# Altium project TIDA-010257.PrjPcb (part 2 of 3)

## Sheet EMCInputFilter.SchDoc: EMC Input Filter
size 431 x 279 mm; Date: Not shown in title block; ApprovedBy: Not shown in title block; CheckedBy: Not shown in title block; Author: Not shown in title block; CompanyName: Not shown in title block; Engineer: Not shown in title block; Organization: Not shown in title block; Address1: Not shown in title block; Address2: Not shown in title block; Address3: Not shown in title block; Address4: Not shown in title block; DocumentNumber: 1; Revision: Use project parameter SCH_Rev; SheetNumber: 3; SheetTotal: 11; PageSetup: Record=PageOptions¦CenterHorizontal=True¦CenterVertical=True¦PrintScale=1.00¦XCorrection=1.00¦YCorrection=1.00¦PrintKind=0¦BorderSize=5000000¦LeftOffset=0¦BottomOffset=0¦Orientation=2¦PaperLength=1000¦PaperWidth=1000¦Scale=100¦PaperSource=15¦PrintQuality=600¦MediaType=1¦DitherType=10¦PaperKind=Letter¦PrintScaleMode=1
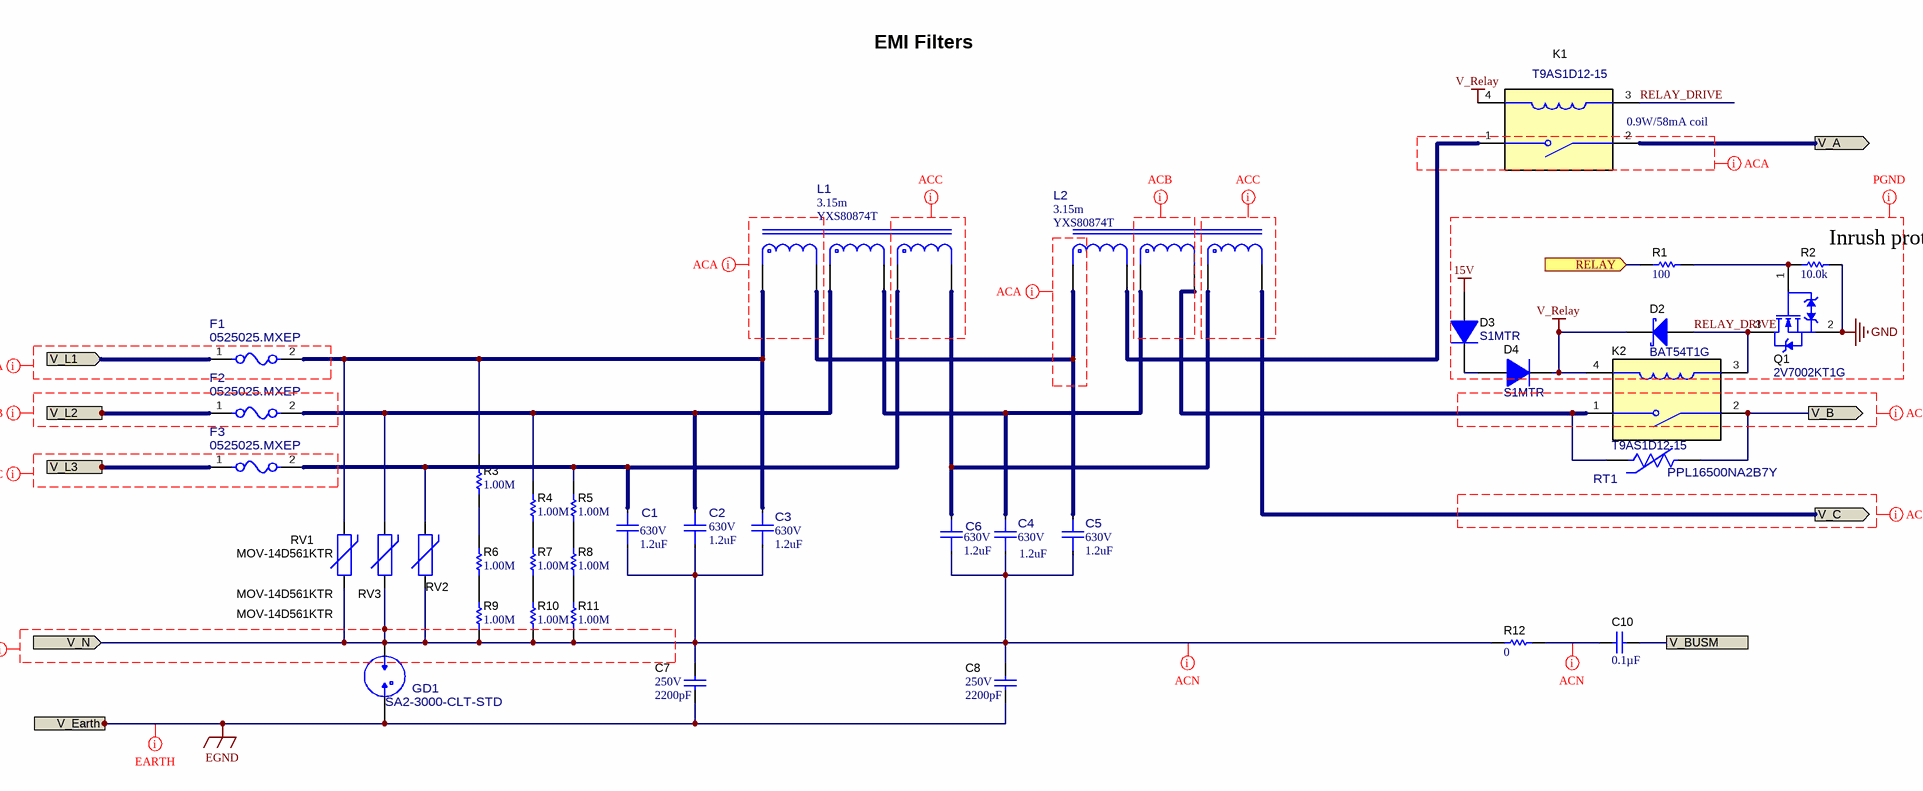
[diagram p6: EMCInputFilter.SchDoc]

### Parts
C1  VDC_V: 630V  ValueDisplayed: 1.2uF  [FP-890334027012CS_RADIAL-MFG]  (hidden comment: 890334027012CS)
C2  VDC_V: 630V  ValueDisplayed: 1.2uF  [FP-890334027012CS_RADIAL-MFG]  (hidden comment: 890334027012CS)
C3  VDC_V: 630V  ValueDisplayed: 1.2uF  [FP-890334027012CS_RADIAL-MFG]  (hidden comment: 890334027012CS)
C4  VDC_V: 630V  ValueDisplayed: 1.2uF  [FP-890334027012CS_RADIAL-MFG]  (hidden comment: 890334027012CS)
C5  VDC_V: 630V  ValueDisplayed: 1.2uF  [FP-890334027012CS_RADIAL-MFG]  (hidden comment: 890334027012CS)
C6  VDC_V: 630V  ValueDisplayed: 1.2uF  [FP-890334027012CS_RADIAL-MFG]  (hidden comment: 890334027012CS)
C7  VDC_V: 250V  ValueDisplayed: 2200pF  [CAPRD1000W60D900H1200]  (hidden comment: DE1E3KX222MA4BL01)
C8  VDC_V: 250V  ValueDisplayed: 2200pF  [CAPRD1000W60D900H1200]  (hidden comment: DE1E3KX222MA4BL01)
C10  ValueDisplayed: 0.1µF  [WCAP-FTXX_P15PL20_1800x600]  (hidden comment: 890334025017)
D2  BAT54T1G  [SOD-123]
D3  S1MTR  [SMA]
D4  S1MTR  [SMA]
F1  0525025.MXEP  [FP-0525025.MXEP_AXIAL-MFG]
F2  0525025.MXEP  [FP-0525025.MXEP_AXIAL-MFG]
F3  0525025.MXEP  [FP-0525025.MXEP_AXIAL-MFG]
GD1  SA2-3000-CLT-STD  [FP-SA2-3000-CLT-STD_AXIAL-MFG]
K1  T9AS1D12-15  [Relay_T9AS1D12]
K2  T9AS1D12-15  [Relay_T9AS1D12]
L1  DCR_ohm: 3.15m  [FP-YXS80874T_PTH_CMC_66MM0_56MM0-MFG]  (hidden comment: YXS80874T)
L2  DCR_ohm: 3.15m  [FP-YXS80874T_PTH_CMC_66MM0_56MM0-MFG]  (hidden comment: YXS80874T)
Q1  2V7002KT1G  [SOT-23]
R1  ValueDisplayed: 100  [0603]  (hidden comment: RC0603FR-07100RL)
R2  ValueDisplayed: 10.0k  [0603]  (hidden comment: RC0603FR-0710KL)
R3  ValueDisplayed: 1.00M  [0805_HV]  (hidden comment: ERJ-6ENF1004V)
R4  ValueDisplayed: 1.00M  [0805_HV]  (hidden comment: ERJ-6ENF1004V)
R5  ValueDisplayed: 1.00M  [0805_HV]  (hidden comment: ERJ-6ENF1004V)
R6  ValueDisplayed: 1.00M  [0805_HV]  (hidden comment: ERJ-6ENF1004V)
R7  ValueDisplayed: 1.00M  [0805_HV]  (hidden comment: ERJ-6ENF1004V)
R8  ValueDisplayed: 1.00M  [0805_HV]  (hidden comment: ERJ-6ENF1004V)
R9  ValueDisplayed: 1.00M  [0805_HV]  (hidden comment: ERJ-6ENF1004V)
R10  ValueDisplayed: 1.00M  [0805_HV]  (hidden comment: ERJ-6ENF1004V)
R11  ValueDisplayed: 1.00M  [0805_HV]  (hidden comment: ERJ-6ENF1004V)
R12  ValueDisplayed: 0  [0603]  (hidden comment: RC0603JR-070RL)
RT1  PPL16500NA2B7Y  [FP-PPL16500NA2B7Y_RADIAL-MFG]
RV1  MOV-14D561KTR  [Bourns_MOV-14D561K]
RV2  MOV-14D561KTR  [Bourns_MOV-14D561K]
RV3  MOV-14D561KTR  [Bourns_MOV-14D561K]

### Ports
RELAY (in), V_A (out), V_B (out), V_BUSM, V_C (out), V_Earth (in), V_L1 (in), V_L2 (in), V_L3 (in), V_N (in)

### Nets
15V: D3.2(A)
EGND: C7.2 C8.2 GD1.1 ; port V_Earth
GND: Q1.2(S) R2.2  [project net VBUSN]
V_Relay: D2.1(K) D4.1(K) K1.4 K2.4
VBUSM: C10.2 ; port V_BUSM
RELAY: R1.2 ; port RELAY
RELAY_DRIVE: D2.2(A) K1.3 K2.3 Q1.3(D)
V_A: K1.2 ; port V_A
V_B: K2.2 RT1.2 ; port V_B
V_C: L2.6 ; port V_C
V_L1: F1.1 ; port V_L1
V_L2: F2.1 ; port V_L2
V_L3: F3.1 ; port V_L3
VN: C1.1 C2.1 C3.1 C4.1 C5.1 C6.1 C7.1 C8.1 GD1.2 R9.1 R10.1 R11.1 R12.2 RV1.1 RV2.1 RV3.1 ; port V_N
NetC1_2: C1.2 F3.2 L1.5 R5.2 RV2.2
NetC2_2: C2.2 F2.2 L1.3 R4.2 RV3.2
NetC3_2: C3.2 F1.2 L1.1 R3.2 RV1.2
NetC4_2: C4.2 L1.4 L2.3
NetC5_2: C5.2 L1.2 L2.1
NetC6_2: C6.2 L1.6 L2.5
NetC10_1: C10.1 R12.1
NetD3_1: D3.1(K) D4.2(A)
NetK1_1: K1.1 L2.2
NetK2_1: K2.1 L2.4 RT1.1
NetQ1_1: Q1.1(G) R1.1 R2.1
NetR3_1: R3.1 R6.2
NetR4_1: R4.1 R7.2
NetR5_1: R5.1 R8.2
NetR6_1: R6.1 R9.2
NetR7_1: R7.1 R10.2
NetR8_1: R8.1 R11.2

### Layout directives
net class ACA: (no net found under the mark)
net class ACB: (no net found under the mark)
net class ACC: (no net found under the mark)
net class ACN: (no net found under the mark), NetC10_1, VN
net class EARTH: EGND
net class PGND: 15V, GND, RELAY_DRIVE, V_Relay

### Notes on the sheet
- EMI Filters
- (near K1) 0.9W/58mA coil
- Inrush protect

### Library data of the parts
C1-C6 = CMP-0090546-1: 1.2µF Film Capacitor 310V  Polypropylene (PP), Metallized Radial; Manufacturer: Wurth Electronics; AEC Qualified: No; Tolerance_%: 10%; SizeZ_mm: 22.5mm
C7 C8 = CMP-0009601-1: CAP, CERM, 2200 pF, 250 V, +/- 20%, E, Cap, 7x12x9 mm; Manufacturer: MuRata; TaMin_C: -25°C; Polarized: N; SizeAreaWB_mm2: 121.5; Value1: Unknown; U/M: EA; Value: 2200pF; TaMax_C: 85°C; SizeZ_mm: 12.5; SizeX_mm: 11.5; SizeY_mm: 7; SizeArea_mm2: 80.5; Cap_F: 2.2nF; AEC Category: Q200
C10 = CMP-0860742-1: CAP, Film, 0.1 µF, 310 VAC/ VDC,+/- 10%, TH; Manufacturer: Wurth Elektronik; VAC: 310; SizeZ_mm: 12.5; Cap_F: 100nF; Polarized: N; SizeArea_mm2: 108; SizeX_mm: 18; TaMax_C: 105°C; SizeAreaWB_mm2: 160; Value: 0.1uF; Cap_Case: 18x6x12mm; TaMin_C: -40°C; AEC Category: Q200; SizeY_mm: 6
D2 = CMP-0028457-2: Diode, Schottky, 30 V, 0.2 A, SOD-123; Manufacturer: ON Semiconductor; SizeArea_mm2: 6.545; Io_A: 200mA; SizeX_mm: 3.85; Value1: 0.2A; SizeY_mm: 1.7; AEC Category: Q101; Vf_V: 800mV; TJmax_C: 125°C; Green_Lifecycle: Not Set; RJC_CperW: 174; Value: 30V; Value2: 0.8V; SizeAreaWB_mm2: 13.095; Green_REACh: Incomplete; SizeZ_mm: 1.35
D3 D4 = CMP-0078438-2: Diode, Standard Recovery Rectifier, 1000 V, 1 A, SMA; Manufacturer: SMC Diode Solutions; Vf_V: 1.1V; TJmax_C: 175°C; SizeZ_mm: 2.87; SizeY_mm: 2.92; AEC Qualified: N; Vr_V: 1kV; Value1: 1A; SizeAreaWB_mm2: 37.3428; SizeArea_mm2: 16.3228; Value: 1000V; AEC Category: Q101; SizeX_mm: 5.59
F1-F3 = CMP-0090478-2: Manufacturer: Littelfuse; SizeZ_mm: 7.285mm; Fuse Interrupt Dc Current: 10000A; AEC Qualified: Yes; Res_ohm: 0.0038Ω; Fuse I2T: 320A2Sec; Fuse Current: 25A; AEC Grade: Grade 1; Interrupt_DC: 10kA; VDC_V: 450V
GD1 = CMP-0089811-1: Gas Discharge Tube 3000V 5000A (5kA) ±20% 2 Pole Through Hole; Manufacturer: Bourns; SizeZ_mm: 8.6mm; AEC Qualified: No
K1 K2 = CMP-0078608-2: Relay, SPST-NO (1 Form A), 30 A, 15 V, TH; Manufacturer: TE Connectivity; Contact Rating_A: 30A; Turn On Voltage (Max)_VDC: 11.25V; Coil Power_W: 1W; Coil Resistance_ohm: 225; SizeAreaWB_mm2: 1015.6293; Time Operate (s): 15ms; Coil Current_A: 66.7mA; SizeZ_mm: 20.4; SizeX_mm: 32.51; SizeY_mm: 27.43; SizeArea_mm2: 891.7493; Turn Off Voltage (Min)_VDC: 1.5V; Coil Type: Non Latching; Coil Voltage_VDC: 15V
L1 L2 = CMP-0122552-1: 3 PHASES COMMON MODE CHOKE; Manufacturer: YAXIN ELECTRONICS; SizeZ_mm: 66mm; AEC Qualified: No
Q1 = CMP-0000777-1: MOSFET, N-CH, 60 V, 0.32 A, AEC-Q101, SOT-23; Alternate Manufacturer: None; Manufacturer: ON Semiconductor; SizeZ_mm: 1.1; ChType: N; Value2: 0.7 nC; Value1: 2; VdsMax_V: 60V; SizeX_mm: 2.5; SizeY_mm: 3; Vgs_V: 20V; AEC Qualified: Y; Value: 60V; SizeArea_mm2: 7.5; AEC Category: Q101; IdsMax_A: 320mA; SizeAreaWB_mm2: 14; U/M: EA; QgTyp_nC: 0.7
R1 = CMP-0022736-4: RES, 100, 1%, 0.1 W, 0603; Manufacturer: Yageo; Power_W: 100mW; TempCo: 100 ppm/C; Value_Code: 100R; Value: 100; EIA_Code: E96; SizeX_mm: 1.6; SizeY_mm: 0.8; SizeZ_mm: 1; Value2: 0.1W; SizeArea_mm2: 1.28; AEC Qualified: N; VDC_V: 75V; AEC Category: Q200; SizeAreaWB_mm2: 4.68
R2 = CMP-0022746-5: RES, 10.0 k, 1%, 0.1 W, 0603; Manufacturer: Yageo; Power_W: 100mW; TempCo: 100 ppm/C; Value_Code: 10k0; Value: 10.0k; EIA_Code: E96; Res_ohm: 10k; SizeX_mm: 1.6; SizeY_mm: 0.8; SizeZ_mm: 1; Value2: 0.1W; SizeArea_mm2: 1.28; AEC Qualified: N; VDC_V: 75V; AEC Category: Q200; SizeAreaWB_mm2: 4.68
R3-R11 = CMP-0021522-3: RES, 1.00 M, 1%, 0.125 W, AEC-Q200 Grade 0, 0805; Manufacturer: Panasonic; Power_W: 125mW; TempCo: 100 ppm/C; Value_Code: 1M00; Value: 1.00Meg; EIA_Code: E96; Res_ohm: 1M; SizeX_mm: 2; SizeY_mm: 1.25; SizeZ_mm: 1.45; Value2: 0.125W; SizeArea_mm2: 2.5; AEC Qualified: Y; AEC Category: Q200; AEC Grade: 0; SizeAreaWB_mm2: 6.75
R12 = CMP-0025885-5: RES, 0, 5%, 0.1 W, 0603; Manufacturer: Yageo; Power_W: 100mW; TempCo: 200 ppm/C; Value_Code: 0000; Value: 0; EIA_Code: E24; SizeX_mm: 1.6; SizeZ_mm: 1; Value2: 0.1W; SizeArea_mm2: 1.28; AEC Qualified: N; VDC_V: 75V; AEC Category: Q200; SizeY_mm: 0.8; SizeAreaWB_mm2: 4.68
RT1 = CMP-0123150-1: Ceramic PTC Thermistor; Manufacturer: Thinking Electronic; SizeZ_mm: 21.5mm; Value: 50Ω; AEC Qualified: No; Tolerance_%: 30%; VDC_V: 270V
RV1-RV3 = CMP-0065393-2: VARISTOR 560V 4.5KA, TH; Manufacturer: Bourns; SizeAreaWB_mm2: 148.0; SizeZ_mm: 22.0; SizeX_mm: 16.5; SizeY_mm: 6.0; SizeArea_mm2: 99.0

## Sheet InputVoltageSensing.SchDoc: Input Voltage Sensing
size A4; Date: Not shown in title block; ApprovedBy: Not shown in title block; CheckedBy: Not shown in title block; Author: Not shown in title block; CompanyName: Not shown in title block; DrawnBy: Hely Zhang; Engineer: Not shown in title block; Organization: Not shown in title block; Address1: Not shown in title block; Address2: Not shown in title block; Address3: Not shown in title block; Address4: Not shown in title block; DocumentNumber: 1; Revision: Use project parameter SCH_Rev; SheetNumber: 7; SheetTotal: 11; PageSetup: Record=PageOptions¦CenterHorizontal=True¦CenterVertical=True¦PrintScale=1.00¦XCorrection=1.00¦YCorrection=1.00¦PrintKind=0¦BorderSize=5000000¦LeftOffset=0¦BottomOffset=0¦Orientation=2¦PaperLength=1000¦PaperWidth=1000¦Scale=100¦PaperSource=15¦PrintQuality=600¦MediaType=1¦DitherType=10¦PaperKind=Letter¦PrintScaleMode=1
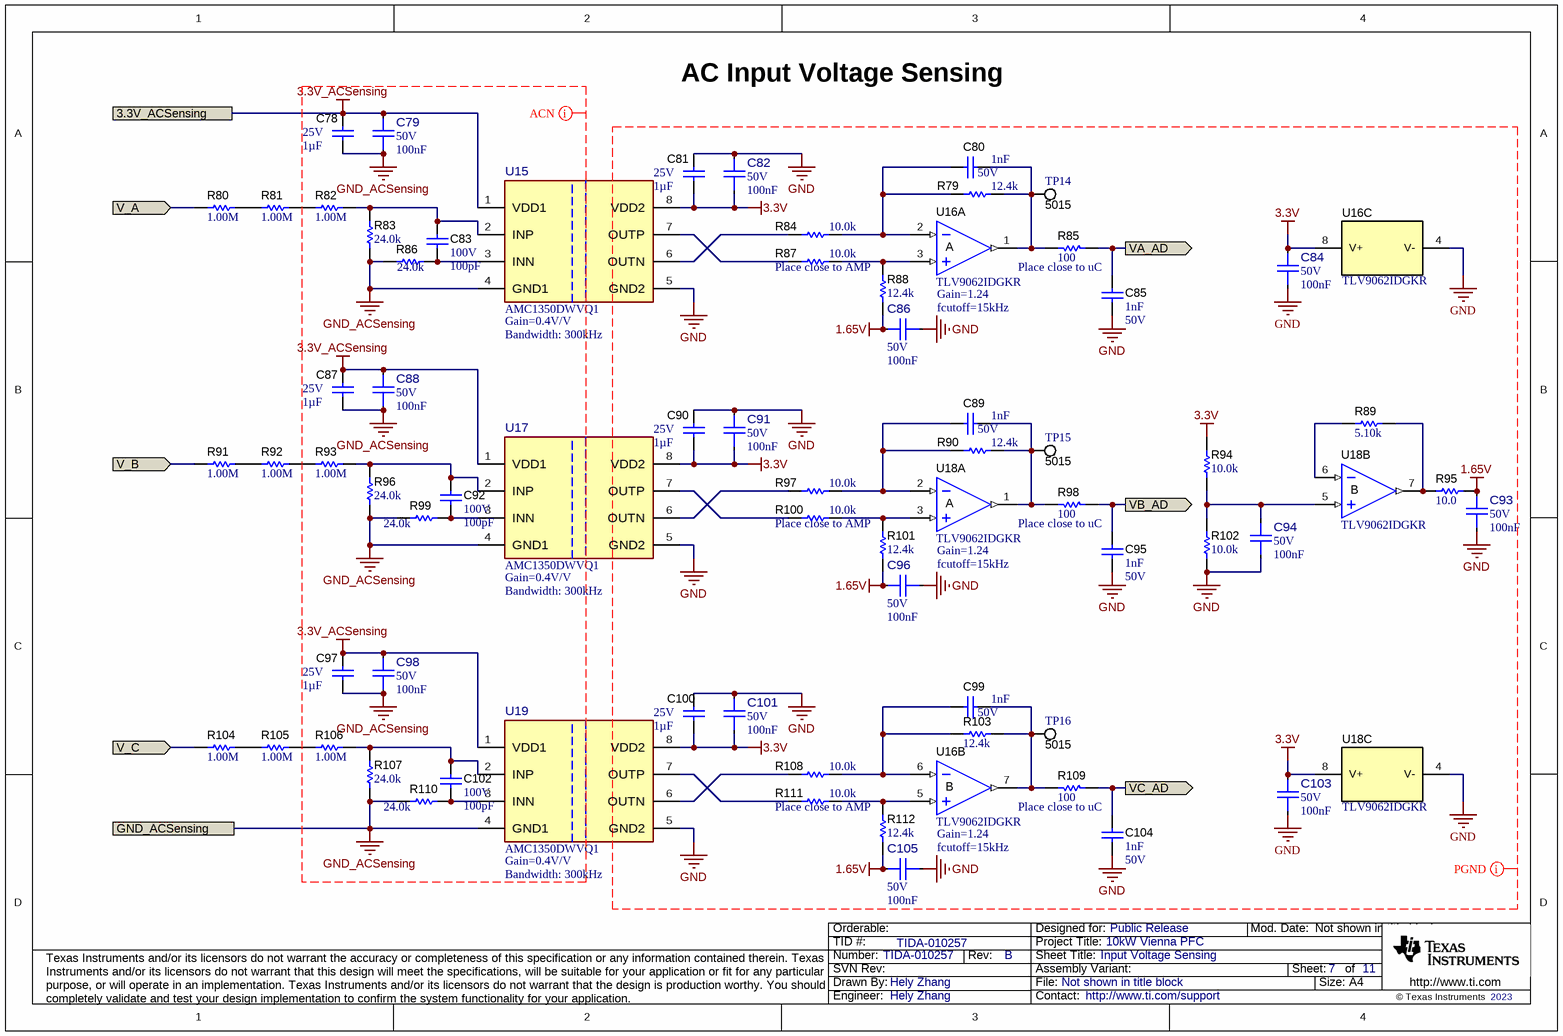
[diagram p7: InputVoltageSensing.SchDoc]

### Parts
C78  VDC_V: 25V  Cap_F: 1µF  [0603]  (hidden comment: GRJ188R71E105KE11D)
C79  VDC_V: 50V  Cap_F: 100nF  [FP-GCM188R71H104KA57J_0603-MFG]  (hidden comment: GCM188R71H104KA57J)
C80  Cap_F: 1nF  VDC_V: 50V  [0603]  (hidden comment: GRM188R71H102KA01D)
C81  VDC_V: 25V  Cap_F: 1µF  [0603]  (hidden comment: GRJ188R71E105KE11D)
C82  VDC_V: 50V  Cap_F: 100nF  [FP-GCM188R71H104KA57J_0603-MFG]  (hidden comment: GCM188R71H104KA57J)
C83  VDC_V: 100V  ValueDisplayed: 100pF  [0603]  (hidden comment: GRM1885C2A101JA01D)
C84  VDC_V: 50V  Cap_F: 100nF  [FP-GCM188R71H104KA57J_0603-MFG]  (hidden comment: GCM188R71H104KA57J)
C85  Cap_F: 1nF  VDC_V: 50V  [0603]  (hidden comment: GRM188R71H102KA01D)
C86  VDC_V: 50V  Cap_F: 100nF  [FP-GCM188R71H104KA57J_0603-MFG]  (hidden comment: GCM188R71H104KA57J)
C87  VDC_V: 25V  Cap_F: 1µF  [0603]  (hidden comment: GRJ188R71E105KE11D)
C88  VDC_V: 50V  Cap_F: 100nF  [FP-GCM188R71H104KA57J_0603-MFG]  (hidden comment: GCM188R71H104KA57J)
C89  Cap_F: 1nF  VDC_V: 50V  [0603]  (hidden comment: GRM188R71H102KA01D)
C90  VDC_V: 25V  Cap_F: 1µF  [0603]  (hidden comment: GRJ188R71E105KE11D)
C91  VDC_V: 50V  Cap_F: 100nF  [FP-GCM188R71H104KA57J_0603-MFG]  (hidden comment: GCM188R71H104KA57J)
C92  VDC_V: 100V  ValueDisplayed: 100pF  [0603]  (hidden comment: GRM1885C2A101JA01D)
C93  VDC_V: 50V  Cap_F: 100nF  [FP-GCM188R71H104KA57J_0603-MFG]  (hidden comment: GCM188R71H104KA57J)
C94  VDC_V: 50V  Cap_F: 100nF  [FP-GCM188R71H104KA57J_0603-MFG]  (hidden comment: GCM188R71H104KA57J)
C95  Cap_F: 1nF  VDC_V: 50V  [0603]  (hidden comment: GRM188R71H102KA01D)
C96  VDC_V: 50V  Cap_F: 100nF  [FP-GCM188R71H104KA57J_0603-MFG]  (hidden comment: GCM188R71H104KA57J)
C97  VDC_V: 25V  Cap_F: 1µF  [0603]  (hidden comment: GRJ188R71E105KE11D)
C98  VDC_V: 50V  Cap_F: 100nF  [FP-GCM188R71H104KA57J_0603-MFG]  (hidden comment: GCM188R71H104KA57J)
C99  Cap_F: 1nF  VDC_V: 50V  [0603]  (hidden comment: GRM188R71H102KA01D)
C100  VDC_V: 25V  Cap_F: 1µF  [0603]  (hidden comment: GRJ188R71E105KE11D)
C101  VDC_V: 50V  Cap_F: 100nF  [FP-GCM188R71H104KA57J_0603-MFG]  (hidden comment: GCM188R71H104KA57J)
C102  VDC_V: 100V  ValueDisplayed: 100pF  [0603]  (hidden comment: GRM1885C2A101JA01D)
C103  VDC_V: 50V  Cap_F: 100nF  [FP-GCM188R71H104KA57J_0603-MFG]  (hidden comment: GCM188R71H104KA57J)
C104  Cap_F: 1nF  VDC_V: 50V  [0603]  (hidden comment: GRM188R71H102KA01D)
C105  VDC_V: 50V  Cap_F: 100nF  [FP-GCM188R71H104KA57J_0603-MFG]  (hidden comment: GCM188R71H104KA57J)
R79  ValueDisplayed: 12.4k  [0603]  (hidden comment: RC0603FR-0712K4L)
R80  ValueDisplayed: 1.00M  [0805_HV]  (hidden comment: ERJ-6ENF1004V)
R81  ValueDisplayed: 1.00M  [0805_HV]  (hidden comment: ERJ-6ENF1004V)
R82  ValueDisplayed: 1.00M  [0805_HV]  (hidden comment: ERJ-6ENF1004V)
R83  ValueDisplayed: 24.0k  [0603]  (hidden comment: RC0603FR-0724KL)
R84  ValueDisplayed: 10.0k  [0603]  (hidden comment: RC0603FR-0710KL)
R85  ValueDisplayed: 100  [0603]  (hidden comment: RC0603FR-07100RL)
R86  ValueDisplayed: 24.0k  [0603]  (hidden comment: RC0603FR-0724KL)
R87  ValueDisplayed: 10.0k  [0603]  (hidden comment: RC0603FR-0710KL)
R88  ValueDisplayed: 12.4k  [0603]  (hidden comment: RC0603FR-0712K4L)
R89  ValueDisplayed: 5.10k  [0603]  (hidden comment: RC0603FR-075K1L)
R90  ValueDisplayed: 12.4k  [0603]  (hidden comment: RC0603FR-0712K4L)
R91  ValueDisplayed: 1.00M  [0805_HV]  (hidden comment: ERJ-6ENF1004V)
R92  ValueDisplayed: 1.00M  [0805_HV]  (hidden comment: ERJ-6ENF1004V)
R93  ValueDisplayed: 1.00M  [0805_HV]  (hidden comment: ERJ-6ENF1004V)
R94  ValueDisplayed: 10.0k  [0603]  (hidden comment: RC0603FR-0710KL)
R95  ValueDisplayed: 10.0  [0603]  (hidden comment: RC0603FR-0710RL)
R96  ValueDisplayed: 24.0k  [0603]  (hidden comment: RC0603FR-0724KL)
R97  ValueDisplayed: 10.0k  [0603]  (hidden comment: RC0603FR-0710KL)
R98  ValueDisplayed: 100  [0603]  (hidden comment: RC0603FR-07100RL)
R99  ValueDisplayed: 24.0k  [0603]  (hidden comment: RC0603FR-0724KL)
R100  ValueDisplayed: 10.0k  [0603]  (hidden comment: RC0603FR-0710KL)
R101  ValueDisplayed: 12.4k  [0603]  (hidden comment: RC0603FR-0712K4L)
R102  ValueDisplayed: 10.0k  [0603]  (hidden comment: RC0603FR-0710KL)
R103  ValueDisplayed: 12.4k  [0603]  (hidden comment: RC0603FR-0712K4L)
R104  ValueDisplayed: 1.00M  [0805_HV]  (hidden comment: ERJ-6ENF1004V)
R105  ValueDisplayed: 1.00M  [0805_HV]  (hidden comment: ERJ-6ENF1004V)
R106  ValueDisplayed: 1.00M  [0805_HV]  (hidden comment: ERJ-6ENF1004V)
R107  ValueDisplayed: 24.0k  [0603]  (hidden comment: RC0603FR-0724KL)
R108  ValueDisplayed: 10.0k  [0603]  (hidden comment: RC0603FR-0710KL)
R109  ValueDisplayed: 100  [0603]  (hidden comment: RC0603FR-07100RL)
R110  ValueDisplayed: 24.0k  [0603]  (hidden comment: RC0603FR-0724KL)
R111  ValueDisplayed: 10.0k  [0603]  (hidden comment: RC0603FR-0710KL)
R112  ValueDisplayed: 12.4k  [0603]  (hidden comment: RC0603FR-0712K4L)
TP14  5015  [Testpoint_Keystone_Miniature]
TP15  5015  [Testpoint_Keystone_Miniature]
TP16  5015  [Testpoint_Keystone_Miniature]
U15  AMC1350DWVQ1  [DWV0008A-MFG]
U16  TLV9062IDGKR  [DGK0008A_N]  (parts A,B,C of 3)
U17  AMC1350DWVQ1  [DWV0008A-MFG]
U18  TLV9062IDGKR  [DGK0008A_N]  (parts A,B,C of 3)
U19  AMC1350DWVQ1  [DWV0008A-MFG]

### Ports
3.3V_ACSensing, GND_ACSensing, V_A (in), V_B (in), V_C (in), VA_AD (out), VB_AD (out), VC_AD (out)

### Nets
1.65V: C86.2 C93.2 C96.2 C105.2 R88.1 R95.2 R101.1 R112.1
3.3V: C81.2 C82.1 C84.2 C90.2 C91.1 C100.2 C101.1 C103.2 R94.2 U15.8(VDD2) U16.8(V+) U17.8(VDD2) U18.8(V+) U19.8(VDD2)
3.3V_ACSensing: C78.1 C79.2 C87.1 C88.2 C97.1 C98.2 U15.1(VDD1) U17.1(VDD1) U19.1(VDD1) ; port 3.3V_ACSensing
GND: C81.1 C82.2 C84.1 C85.1 C86.1 C90.1 C91.2 C93.1 C94.1 C95.1 C96.1 C100.1 C101.2 C103.1 C104.1 C105.1 R102.1 U15.5(GND2) U16.4(V-) U17.5(GND2) U18.4(V-) U19.5(GND2)  [project net VBUSN]
GND_ACSensing: C78.2 C79.1 C87.2 C88.1 C97.2 C98.1 R83.1 R86.2 R96.2 R99.2 R107.2 R110.2 U15.4(GND1) U17.4(GND1) U19.4(GND1) ; port GND_ACSensing
V_A: R80.1 ; port V_A
V_B: R91.1 ; port V_B
V_C: R104.1 ; port V_C
VA_AD: C85.2 R85.1 ; port VA_AD
VB_AD: C95.2 R98.1 ; port VB_AD
VC_AD: C104.2 R109.1 ; port VC_AD
NetC80_1: C80.1 R79.2 R85.2 TP14.1 U16.1(OUT)
NetC80_2: C80.2 R79.1 R84.2 U16.2(IN-)
NetC83_1: C83.1 R82.2 R83.2 U15.2(INP)
NetC83_2: C83.2 R86.1 U15.3(INN)
NetC89_1: C89.1 R90.2 R98.2 TP15.1 U18.1(OUT)
NetC89_2: C89.2 R90.1 R97.2 U18.2(IN-)
NetC92_1: C92.1 R93.2 R96.1 U17.2(INP)
NetC92_2: C92.2 R99.1 U17.3(INN)
NetC94_2: C94.2 R94.1 R102.2 U18.5(IN+)
NetC99_1: C99.1 R103.2 R109.2 TP16.1 U16.7(OUT)
NetC99_2: C99.2 R103.1 R108.2 U16.6(IN-)
NetC102_1: C102.1 R106.2 R107.1 U19.2(INP)
NetC102_2: C102.2 R110.1 U19.3(INN)
NetR80_2: R80.2 R81.1
NetR81_2: R81.2 R82.1
NetR84_1: R84.1 U15.6(OUTN)
NetR87_1: R87.1 U15.7(OUTP)
NetR87_2: R87.2 R88.2 U16.3(IN+)
NetR89_1: R89.1 R95.1 U18.7(OUT)
NetR89_2: R89.2 U18.6(IN-)
NetR91_2: R91.2 R92.1
NetR92_2: R92.2 R93.1
NetR97_1: R97.1 U17.6(OUTN)
NetR100_1: R100.1 U17.7(OUTP)
NetR100_2: R100.2 R101.2 U18.3(IN+)
NetR104_2: R104.2 R105.1
NetR105_2: R105.2 R106.1
NetR108_1: R108.1 U19.6(OUTN)
NetR111_1: R111.1 U19.7(OUTP)
NetR111_2: R111.2 R112.2 U16.5(IN+)

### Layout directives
net class ACN: 3.3V_ACSensing, GND_ACSensing
net class PGND: 1.65V, 3.3V, GND

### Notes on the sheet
- AC Input Voltage Sensing
- Place close to AMP
- Gain=1.24
- fcutoff=15kHz
- Place close to uC
- (near U15) Gain=0.4V/V
- (near U15) Bandwidth: 300kHz
- (near U17) Gain=0.4V/V
- (near U17) Bandwidth: 300kHz
- (near U19) Gain=0.4V/V
- (near U19) Bandwidth: 300kHz

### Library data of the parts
C78 C81 C87 C90 C97 C100 = CMP-0079720-2: CAP, CERM, 1 µF, 25 V,+/- 10%, X7R, 0603; Manufacturer: MuRata; AEC Category: Q200; TaMin_C: -55°C; AEC Qualified: N; SizeAreaWB_mm2: 4.68; SizeArea_mm2: 1.28; Value: 1uF; SizeZ_mm: 1; SizeX_mm: 1.6; U/M: EA; MFG_Status: TI_Obsolete; SizeY_mm: 0.8; TaMax_C: 125°C
C79 C82 C84 C86 C88 C91 C93 C94 C96 C98 C101 C103 C105 = CMP-0095617-1: 0603 50 V 0.1 uF X7R ±10% Tolerance SMT Multilayer Ceramic Capacitor; Manufacturer: Murata; TempCo: 15%; SizeZ_mm: 0.9mm; AEC Qualified: No; ValueDisplayed: 0.1uF; Value: 100nF
C80 C85 C89 C95 C99 C104 = CMP-0007432-5: CAP, CERM, 1000 pF, 50 V, +/- 10%, X7R, 0603; Manufacturer: MuRata; TaMin_C: -55°C; Polarized: N; SizeAreaWB_mm2: 4.68; Value1: Unknown; U/M: EA; Value: 1000pF; TaMax_C: 125°C; SizeZ_mm: 1; SizeX_mm: 1.6; SizeY_mm: 0.8; SizeArea_mm2: 1.28; AEC Category: Q200
C83 C92 C102 = CMP-0007237-4: CAP, CERM, 100 pF, 100 V, +/- 5%, C0G/NP0, 0603; Manufacturer: MuRata; TaMin_C: -55°C; Polarized: N; SizeAreaWB_mm2: 4.68; Value1: Unknown; U/M: EA; Value: 100pF; TaMax_C: 125°C; SizeZ_mm: 1; SizeX_mm: 1.6; SizeY_mm: 0.8; SizeArea_mm2: 1.28; AEC Category: Q200
R79 R88 R90 R101 R103 R112 = CMP-0022777-5: RES, 12.4 k, 1%, 0.1 W, 0603; Manufacturer: Yageo; Power_W: 100mW; TempCo: 100 ppm/C; Value_Code: 12k4; Value: 12.4k; EIA_Code: E96; SizeX_mm: 1.6; SizeY_mm: 0.8; SizeZ_mm: 1; Value2: 0.1W; SizeArea_mm2: 1.28; AEC Qualified: N; VDC_V: 75V; AEC Category: Q200; SizeAreaWB_mm2: 4.68
R80-R82 R91-R93 R104-R106 = CMP-0021522-3: as R3-R11 on sheet EMCInputFilter
R83 R86 R96 R99 R107 R110 = CMP-0022945-5: RES, 24.0 k, 1%, 0.1 W, 0603; Manufacturer: Yageo; Power_W: 100mW; TempCo: 100 ppm/C; Value_Code: 24k0; Value: 24.0k; Res_ohm: 24k; SizeX_mm: 1.6; SizeY_mm: 0.8; SizeZ_mm: 1; Value2: 0.1W; SizeArea_mm2: 1.28; AEC Qualified: N; VDC_V: 75V; AEC Category: Q200; SizeAreaWB_mm2: 4.68
R84 R87 R94 R97 R100 R102 R108 R111 = CMP-0022746-5: as R2 on sheet EMCInputFilter
R85 R98 R109 = CMP-0022736-4: as R1 on sheet EMCInputFilter
R89 = CMP-0023198-5: RES, 5.10 k, 1%, 0.1 W, 0603; Manufacturer: Yageo; Power_W: 100mW; TempCo: 100 ppm/C; Value_Code: 5k10; Value: 5.10k; Res_ohm: 5.1k; SizeX_mm: 1.6; SizeY_mm: 0.8; SizeZ_mm: 1; Value2: 0.1W; SizeArea_mm2: 1.28; AEC Qualified: N; VDC_V: 75V; AEC Category: Q200; SizeAreaWB_mm2: 4.68
R95 = CMP-0022751-4: RES, 10.0, 1%, 0.1 W, 0603; Manufacturer: Yageo; Power_W: 100mW; TempCo: 100 ppm/C; Value_Code: 10R0; Value: 10.0; EIA_Code: E96; Res_ohm: 10; SizeX_mm: 1.6; SizeY_mm: 0.8; SizeZ_mm: 1; Value2: 0.1W; SizeArea_mm2: 1.28; AEC Qualified: N; VDC_V: 75V; AEC Category: Q200; SizeAreaWB_mm2: 4.68
TP14-TP16 = CMP-0055152-2: Test Point, Miniature, SMT; Manufacturer: Keystone Electronics; CT: TRUE; Green_Lifecycle: Active; Green_REACh: Passed; CNHeader: FALSE
U15 U17 U19 = CMP-0092814-1: Precision, ±5-V Input, Reinforced Isolated Amplifier; Manufacturer: Texas Instruments; Bandwidth: 275kHz; Input Bias Current: 0.0035uA; SizeZ_mm: 2.8mm; Output Current Per Channel: 14mA; TaMax_C: +125°C; Input Offset Voltage: 0.4mV; TaMin_C: -55°C; Standoff Height: 0.36mm; Min Supply Voltage: 3V; TJmax_C: +150°C; AEC Qualified: No; Max Supply Voltage: 5.5V; Number Of Channels: 1
U16 U18 = CMP-0084063-1: 10-MHz, Low-Noise, RRIO, CMOS Operational Amplifier for Cost-Sensitive Systems, DGK0008A (VSSOP-8); Manufacturer: Texas Instruments; Alternate PartNumber: TLV9062IDGKT; Rating: Catalog; SizeAreaWB_mm2: 23.6; SizeArea_mm2: 14.7; AEC Qualified: N; AEC Category: Q200; SizeZ_mm: 1.1; SizeY_mm: 3; CompType: IC; SizeX_mm: 4.9

## Sheet OutputVoltageSensing.SchDoc: OutputVoltageSensing
size A4; Date: Not shown in title block; ApprovedBy: Not shown in title block; CheckedBy: Not shown in title block; Author: Not shown in title block; CompanyName: Not shown in title block; DrawnBy: Hely Zhang; Engineer: Not shown in title block; Organization: Not shown in title block; Address1: Not shown in title block; Address2: Not shown in title block; Address3: Not shown in title block; Address4: Not shown in title block; DocumentNumber: 1; Revision: Use project parameter SCH_Rev; SheetNumber: 8; SheetTotal: 11; PageSetup: Record=PageOptions¦CenterHorizontal=True¦CenterVertical=True¦PrintScale=1.00¦XCorrection=1.00¦YCorrection=1.00¦PrintKind=0¦BorderSize=5000000¦LeftOffset=0¦BottomOffset=0¦Orientation=2¦PaperLength=1000¦PaperWidth=1000¦Scale=100¦PaperSource=15¦PrintQuality=600¦MediaType=1¦DitherType=10¦PaperKind=Letter¦PrintScaleMode=1
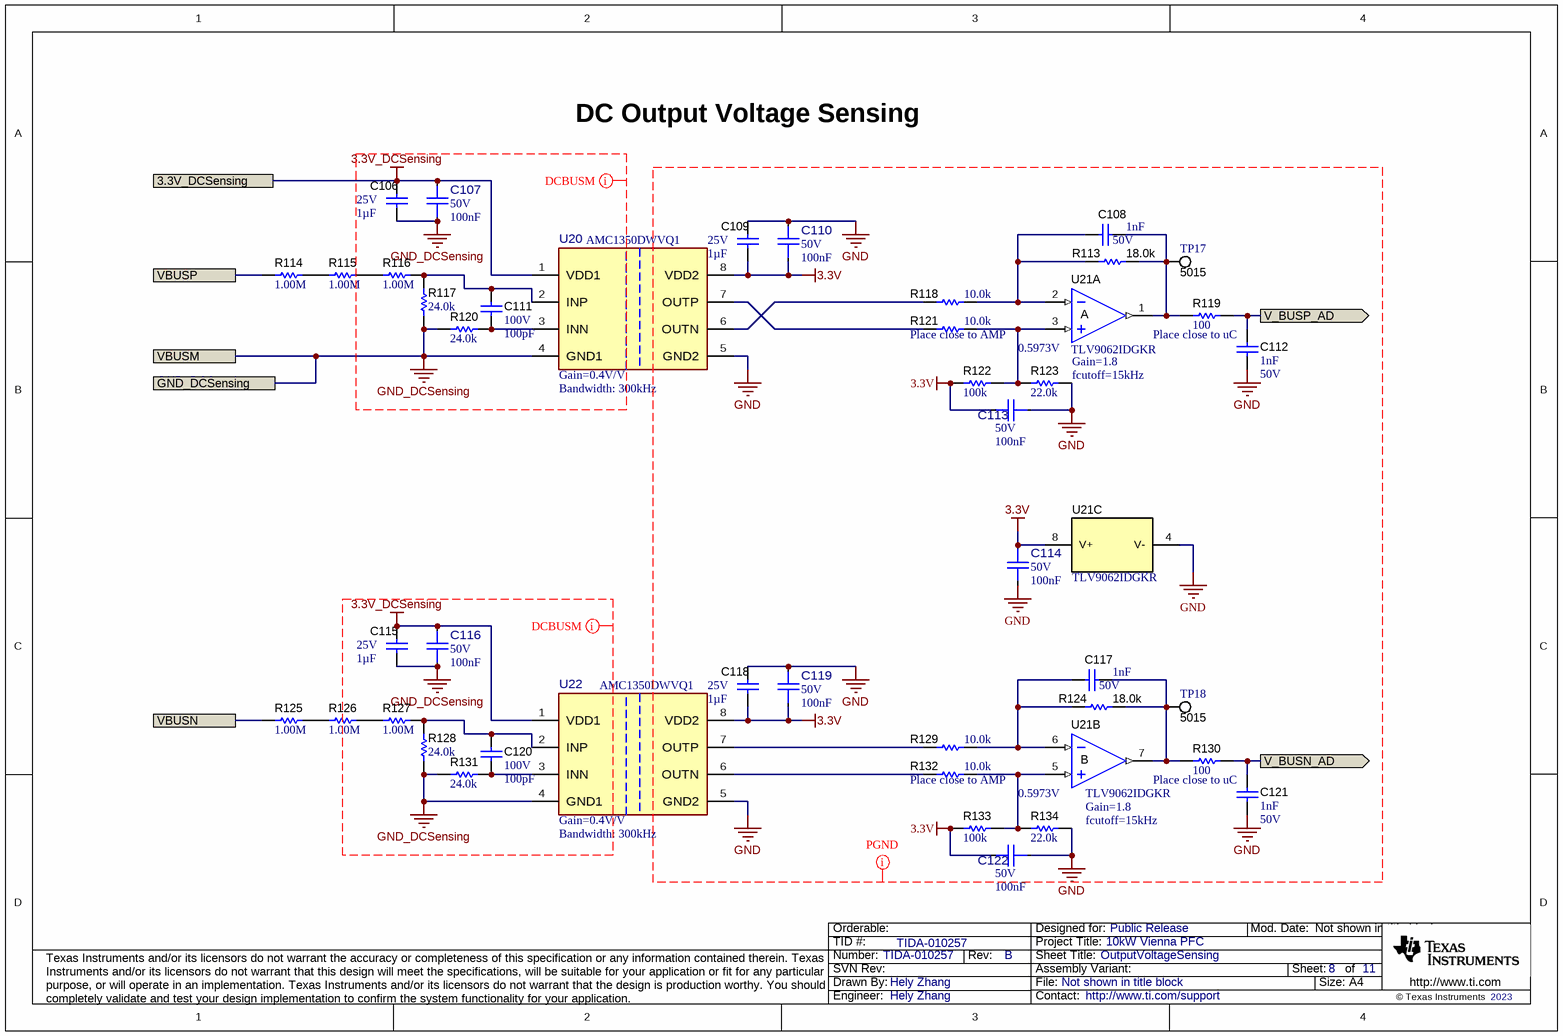
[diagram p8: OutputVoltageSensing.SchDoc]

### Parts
C106  VDC_V: 25V  Cap_F: 1µF  [0603]  (hidden comment: GRJ188R71E105KE11D)
C107  VDC_V: 50V  Cap_F: 100nF  [FP-GCM188R71H104KA57J_0603-MFG]  (hidden comment: GCM188R71H104KA57J)
C108  Cap_F: 1nF  VDC_V: 50V  [0603]  (hidden comment: GRM188R71H102KA01D)
C109  VDC_V: 25V  Cap_F: 1µF  [0603]  (hidden comment: GRJ188R71E105KE11D)
C110  VDC_V: 50V  Cap_F: 100nF  [FP-GCM188R71H104KA57J_0603-MFG]  (hidden comment: GCM188R71H104KA57J)
C111  VDC_V: 100V  ValueDisplayed: 100pF  [0603]  (hidden comment: GRM1885C2A101JA01D)
C112  Cap_F: 1nF  VDC_V: 50V  [0603]  (hidden comment: GRM188R71H102KA01D)
C113  VDC_V: 50V  Cap_F: 100nF  [FP-GCM188R71H104KA57J_0603-MFG]  (hidden comment: GCM188R71H104KA57J)
C114  VDC_V: 50V  Cap_F: 100nF  [FP-GCM188R71H104KA57J_0603-MFG]  (hidden comment: GCM188R71H104KA57J)
C115  VDC_V: 25V  Cap_F: 1µF  [0603]  (hidden comment: GRJ188R71E105KE11D)
C116  VDC_V: 50V  Cap_F: 100nF  [FP-GCM188R71H104KA57J_0603-MFG]  (hidden comment: GCM188R71H104KA57J)
C117  Cap_F: 1nF  VDC_V: 50V  [0603]  (hidden comment: GRM188R71H102KA01D)
C118  VDC_V: 25V  Cap_F: 1µF  [0603]  (hidden comment: GRJ188R71E105KE11D)
C119  VDC_V: 50V  Cap_F: 100nF  [FP-GCM188R71H104KA57J_0603-MFG]  (hidden comment: GCM188R71H104KA57J)
C120  VDC_V: 100V  ValueDisplayed: 100pF  [0603]  (hidden comment: GRM1885C2A101JA01D)
C121  Cap_F: 1nF  VDC_V: 50V  [0603]  (hidden comment: GRM188R71H102KA01D)
C122  VDC_V: 50V  Cap_F: 100nF  [FP-GCM188R71H104KA57J_0603-MFG]  (hidden comment: GCM188R71H104KA57J)
R113  ValueDisplayed: 18.0k  [0603]  (hidden comment: RC0603FR-0718KL)
R114  ValueDisplayed: 1.00M  [0805_HV]  (hidden comment: ERJ-6ENF1004V)
R115  ValueDisplayed: 1.00M  [0805_HV]  (hidden comment: ERJ-6ENF1004V)
R116  ValueDisplayed: 1.00M  [0805_HV]  (hidden comment: ERJ-6ENF1004V)
R117  ValueDisplayed: 24.0k  [0603]  (hidden comment: RC0603FR-0724KL)
R118  ValueDisplayed: 10.0k  [0603]  (hidden comment: RC0603FR-0710KL)
R119  ValueDisplayed: 100  [0603]  (hidden comment: RC0603FR-07100RL)
R120  ValueDisplayed: 24.0k  [0603]  (hidden comment: RC0603FR-0724KL)
R121  ValueDisplayed: 10.0k  [0603]  (hidden comment: RC0603FR-0710KL)
R122  ValueDisplayed: 100k  [0603]  (hidden comment: RC0603FR-07100KL)
R123  ValueDisplayed: 22.0k  [0603]  (hidden comment: RC0603FR-0722KL)
R124  ValueDisplayed: 18.0k  [0603]  (hidden comment: RC0603FR-0718KL)
R125  ValueDisplayed: 1.00M  [0805_HV]  (hidden comment: ERJ-6ENF1004V)
R126  ValueDisplayed: 1.00M  [0805_HV]  (hidden comment: ERJ-6ENF1004V)
R127  ValueDisplayed: 1.00M  [0805_HV]  (hidden comment: ERJ-6ENF1004V)
R128  ValueDisplayed: 24.0k  [0603]  (hidden comment: RC0603FR-0724KL)
R129  ValueDisplayed: 10.0k  [0603]  (hidden comment: RC0603FR-0710KL)
R130  ValueDisplayed: 100  [0603]  (hidden comment: RC0603FR-07100RL)
R131  ValueDisplayed: 24.0k  [0603]  (hidden comment: RC0603FR-0724KL)
R132  ValueDisplayed: 10.0k  [0603]  (hidden comment: RC0603FR-0710KL)
R133  ValueDisplayed: 100k  [0603]  (hidden comment: RC0603FR-07100KL)
R134  ValueDisplayed: 22.0k  [0603]  (hidden comment: RC0603FR-0722KL)
TP17  5015  [Testpoint_Keystone_Miniature]
TP18  5015  [Testpoint_Keystone_Miniature]
U20  AMC1350DWVQ1  [DWV0008A-MFG]
U21  TLV9062IDGKR  [DGK0008A_N]  (parts A,B,C of 3)
U22  AMC1350DWVQ1  [DWV0008A-MFG]

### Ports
3.3V_DCSensing, GND_DCSensing, V_BUSN_AD (out), V_BUSP_AD (out), VBUSM, VBUSN, VBUSP

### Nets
3.3V: C109.2 C110.1 C113.2 C114.1 C118.2 C119.1 C122.2 R122.2 R133.2 U20.8(VDD2) U21.8(V+) U22.8(VDD2)
3.3V_DCSensing: C106.1 C107.2 C115.1 C116.2 U20.1(VDD1) U22.1(VDD1) ; port 3.3V_DCSensing
GND: C109.1 C110.2 C112.1 C113.1 C114.2 C118.1 C119.2 C121.1 C122.1 R123.2 R125.1 R134.2 U20.5(GND2) U21.4(V-) U22.5(GND2) ; port VBUSN  [project net VBUSN]
GND_DCSensing: C106.2 C107.1 C115.2 C116.1 R117.2 R120.2 R128.1 R131.1 U20.4(GND1) U22.4(GND1) ; port VBUSM, port GND_DCSensing  [project net VBUSM]
V_BUSN_AD: C121.2 R130.2 ; port V_BUSN_AD
V_BUSP_AD: C112.2 R119.2 ; port V_BUSP_AD
VBUSP: R114.1 ; port VBUSP
NetC108_1: C108.1 R113.1 R119.1 TP17.1 U21.1(OUT)
NetC108_2: C108.2 R113.2 R118.2 U21.2(IN-)
NetC111_1: C111.1 R116.2 R117.1 U20.2(INP)
NetC111_2: C111.2 R120.1 U20.3(INN)
NetC117_1: C117.1 R124.1 R130.1 TP18.1 U21.7(OUT)
NetC117_2: C117.2 R124.2 R129.2 U21.6(IN-)
NetC120_1: C120.1 R127.2 R128.2 U22.2(INP)
NetC120_2: C120.2 R131.2 U22.3(INN)
NetR114_2: R114.2 R115.1
NetR115_2: R115.2 R116.1
NetR118_1: R118.1 U20.6(OUTN)
NetR121_1: R121.1 U20.7(OUTP)
NetR121_2: R121.2 R122.1 R123.1 U21.3(IN+)
NetR125_2: R125.2 R126.1
NetR126_2: R126.2 R127.1
NetR129_1: R129.1 U22.7(OUTP)
NetR132_1: R132.1 U22.6(OUTN)
NetR132_2: R132.2 R133.1 R134.1 U21.5(IN+)

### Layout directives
net class DCBUSM: 3.3V_DCSensing, GND_DCSensing
net class PGND: 3.3V, GND

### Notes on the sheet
- DC Output Voltage Sensing
- (near U20) Gain=0.4V/V
- (near R121) Place close to AMP
- 0.5973V
- Gain=1.8
- (near R123) fcutoff=15kHz
- (near C112) Place close to uC
- (near U20) Bandwidth: 300kHz
- (near R132) Place close to AMP
- (near C121) Place close to uC
- (near U22) Gain=0.4V/V
- (near U22) Bandwidth: 300kHz
- fcutoff=15kHz

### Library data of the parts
C106 C109 C115 C118 = CMP-0079720-2: as C78 on sheet InputVoltageSensing
C107 C110 C113 C114 C116 C119 C122 = CMP-0095617-1: as C79 on sheet InputVoltageSensing
C108 C112 C117 C121 = CMP-0007432-5: as C80 on sheet InputVoltageSensing
C111 C120 = CMP-0007237-4: as C83 on sheet InputVoltageSensing
R113 R124 = CMP-0022852-5: RES, 18.0 k, 1%, 0.1 W, 0603; Manufacturer: Yageo; Power_W: 100mW; TempCo: 100 ppm/C; Value_Code: 18k0; Value: 18.0k; Res_ohm: 18k; SizeX_mm: 1.6; SizeY_mm: 0.8; SizeZ_mm: 1; Value2: 0.1W; SizeArea_mm2: 1.28; AEC Qualified: N; VDC_V: 75V; AEC Category: Q200; SizeAreaWB_mm2: 4.68
R114-R116 R125-R127 = CMP-0021522-3: as R3-R11 on sheet EMCInputFilter
R117 R120 R128 R131 = CMP-0022945-5: as R83 on sheet InputVoltageSensing
R118 R121 R129 R132 = CMP-0022746-5: as R2 on sheet EMCInputFilter
R119 R130 = CMP-0022736-4: as R1 on sheet EMCInputFilter
R122 R133 = CMP-0022735-5: RES, 100 k, 1%, 0.1 W, 0603; Manufacturer: Yageo; Power_W: 100mW; TempCo: 100 ppm/C; Value: 100k; EIA_Code: E96; SizeX_mm: 1.6; SizeY_mm: 0.8; SizeZ_mm: 1; Value2: 0.1W; SizeArea_mm2: 1.28; AEC Qualified: N; VDC_V: 75V; AEC Category: Q200; SizeAreaWB_mm2: 4.68
R123 R134 = CMP-0022925-5: RES, 22.0 k, 1%, 0.1 W, 0603; Manufacturer: Yageo; Power_W: 100mW; TempCo: 100 ppm/C; Value_Code: 22k0; Value: 22.0k; Res_ohm: 22k; SizeX_mm: 1.6; SizeY_mm: 0.8; SizeZ_mm: 1; Value2: 0.1W; SizeArea_mm2: 1.28; AEC Qualified: N; VDC_V: 75V; AEC Category: Q200; SizeAreaWB_mm2: 4.68
TP17 TP18 = CMP-0055152-2: as TP14-TP16 on sheet InputVoltageSensing
U20 U22 = CMP-0092814-1: as U15 on sheet InputVoltageSensing
U21 = CMP-0084063-1: as U16 on sheet InputVoltageSensing

## Sheet Controller.SchDoc: Controller
size A4; Date: Not shown in title block; ApprovedBy: Not shown in title block; CheckedBy: Not shown in title block; Author: Not shown in title block; CompanyName: Not shown in title block; DrawnBy: Hely Zhang; Engineer: Not shown in title block; Organization: Not shown in title block; Address1: Not shown in title block; Address2: Not shown in title block; Address3: Not shown in title block; Address4: Not shown in title block; DocumentNumber: 1; Revision: Use project parameter SCH_Rev; SheetNumber: 9; SheetTotal: 11; PageSetup: Record=PageOptions¦CenterHorizontal=True¦CenterVertical=True¦PrintScale=1.00¦XCorrection=1.00¦YCorrection=1.00¦PrintKind=0¦BorderSize=5000000¦LeftOffset=0¦BottomOffset=0¦Orientation=2¦PaperLength=1000¦PaperWidth=1000¦Scale=100¦PaperSource=15¦PrintQuality=600¦MediaType=1¦DitherType=10¦PaperKind=Letter¦PrintScaleMode=1
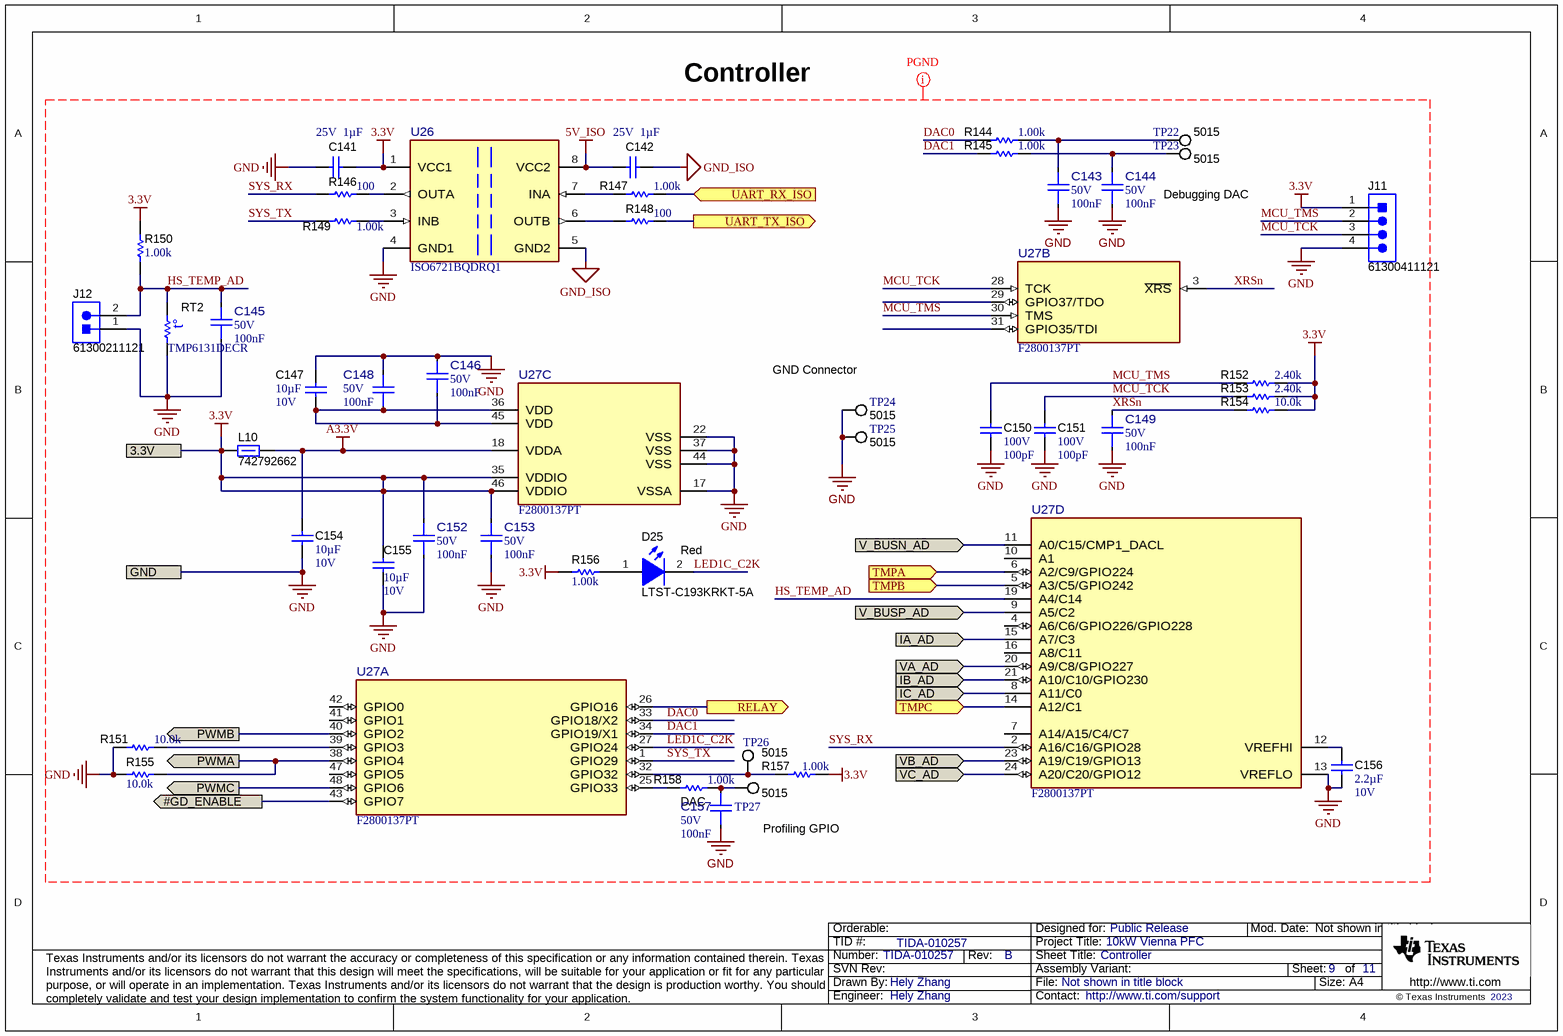
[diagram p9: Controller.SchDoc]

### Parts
C141  VDC_V: 25V  Cap_F: 1µF  [0603]  (hidden comment: GRJ188R71E105KE11D)
C142  VDC_V: 25V  Cap_F: 1µF  [0603]  (hidden comment: GRJ188R71E105KE11D)
C143  VDC_V: 50V  Cap_F: 100nF  [FP-GCM188R71H104KA57J_0603-MFG]  (hidden comment: GCM188R71H104KA57J)
C144  VDC_V: 50V  Cap_F: 100nF  [FP-GCM188R71H104KA57J_0603-MFG]  (hidden comment: GCM188R71H104KA57J)
C145  VDC_V: 50V  Cap_F: 100nF  [FP-GCM188R71H104KA57J_0603-MFG]  (hidden comment: GCM188R71H104KA57J)
C146  VDC_V: 50V  Cap_F: 100nF  [FP-GCM188R71H104KA57J_0603-MFG]  (hidden comment: GCM188R71H104KA57J)
C147  Cap_F: 10µF  VDC_V: 10V  [0603]  (hidden comment: GRM188Z71A106MA73D)
C148  VDC_V: 50V  Cap_F: 100nF  [FP-GCM188R71H104KA57J_0603-MFG]  (hidden comment: GCM188R71H104KA57J)
C149  VDC_V: 50V  Cap_F: 100nF  [FP-GCM188R71H104KA57J_0603-MFG]  (hidden comment: GCM188R71H104KA57J)
C150  VDC_V: 100V  ValueDisplayed: 100pF  [0603]  (hidden comment: GRM1885C2A101JA01D)
C151  VDC_V: 100V  ValueDisplayed: 100pF  [0603]  (hidden comment: GRM1885C2A101JA01D)
C152  VDC_V: 50V  Cap_F: 100nF  [FP-GCM188R71H104KA57J_0603-MFG]  (hidden comment: GCM188R71H104KA57J)
C153  VDC_V: 50V  Cap_F: 100nF  [FP-GCM188R71H104KA57J_0603-MFG]  (hidden comment: GCM188R71H104KA57J)
C154  Cap_F: 10µF  VDC_V: 10V  [0603]  (hidden comment: GRM188Z71A106MA73D)
C155  Cap_F: 10µF  VDC_V: 10V  [0603]  (hidden comment: GRM188Z71A106MA73D)
C156  Cap_F: 2.2µF  VDC_V: 10V  [0603]  (hidden comment: GRM188R71A225KE15J)
C157  VDC_V: 50V  Cap_F: 100nF  [FP-GCM188R71H104KA57J_0603-MFG]  (hidden comment: GCM188R71H104KA57J)
D25  LTST-C193KRKT-5A  value Red  [LTST-C193_Red]
J11  61300411121  [WURTH_61300411121]
J12  61300211121  [WURTH_61300211121]
L10  742792662  [0603]
R144  ValueDisplayed: 1.00k  [0603]  (hidden comment: RC0603FR-071KL)
R145  ValueDisplayed: 1.00k  [0603]  (hidden comment: RC0603FR-071KL)
R146  ValueDisplayed: 100  [0603]  (hidden comment: RC0603FR-07100RL)
R147  ValueDisplayed: 1.00k  [0603]  (hidden comment: RC0603FR-071KL)
R148  ValueDisplayed: 100  [0603]  (hidden comment: RC0603FR-07100RL)
R149  ValueDisplayed: 1.00k  [0603]  (hidden comment: RC0603FR-071KL)
R150  ValueDisplayed: 1.00k  [0603]  (hidden comment: RC0603FR-071KL)
R151  ValueDisplayed: 10.0k  [0603]  (hidden comment: RC0603FR-0710KL)
R152  ValueDisplayed: 2.40k  [0603]  (hidden comment: RC0603FR-072K4L)
R153  ValueDisplayed: 2.40k  [0603]  (hidden comment: RC0603FR-072K4L)
R154  ValueDisplayed: 10.0k  [0603]  (hidden comment: RC0603FR-0710KL)
R155  ValueDisplayed: 10.0k  [0603]  (hidden comment: RC0603FR-0710KL)
R156  ValueDisplayed: 1.00k  [0603]  (hidden comment: RC0603FR-071KL)
R157  ValueDisplayed: 1.00k  [0603]  (hidden comment: RC0603FR-071KL)
R158  ValueDisplayed: 1.00k  [0603]  (hidden comment: RC0603FR-071KL)
RT2  TMP6131DECR  [DEC0002A]
TP22  5015  [Testpoint_Keystone_Miniature]
TP23  5015  [Testpoint_Keystone_Miniature]
TP24  5015  [Testpoint_Keystone_Miniature]
TP25  5015  [Testpoint_Keystone_Miniature]
TP26  5015  [Testpoint_Keystone_Miniature]
TP27  5015  [Testpoint_Keystone_Miniature]
U26  ISO6721BQDRQ1  [D0008A-MFG]
U27  F2800137PT  [PT0048A-MFG]  (parts A,B,C,D of 4)

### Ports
3.3V, #GD_ENABLE (out), GND, IA_AD (in), IB_AD (in), IC_AD (in), PWMA (out), PWMB (out), PWMC (out), RELAY (out), TMPA (in), TMPB (in), TMPC (in), UART_RX_ISO (in), UART_TX_ISO (out), V_BUSN_AD (in), V_BUSP_AD (in), VA_AD (in), VB_AD (in), VC_AD (in)

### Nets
3.3V: C141.2 C152.2 C153.2 C155.2 J11.1 L10.1 R150.2 R152.2 R153.2 R154.1 R156.1 R157.2 U26.1(VCC1) U27.35(VDDIO) U27.46(VDDIO) ; port 3.3V
5V_ISO: C142.1 U26.8(VCC2)
A3.3V: C154.1 L10.2 U27.18(VDDA)
GND: C141.1 C143.1 C144.1 C145.1 C146.2 C147.1 C148.2 C149.1 C150.2 C151.2 C152.1 C153.1 C154.2 C155.1 C156.2 C157.1 J11.4 J12.1 R151.2 R155.1 RT2.1 TP24.1 TP25.1 U26.4(GND1) U27.13(VREFLO) U27.17(VSSA) U27.22(VSS) U27.37(VSS) U27.44(VSS) ; port GND  [project net VBUSN]
GND_ISO: C142.2 U26.5(GND2)
#GD_ENABLE: U27.43(GPIO7) ; port #GD_ENABLE
DAC0: R144.1 U27.33(GPIO18/X2)
DAC1: R145.1 U27.34(GPIO19/X1)
HS_TEMP_AD: C145.2 J12.2 R150.1 RT2.2 U27.19(A4/C14)
IA_AD: U27.15(A7/C3) ; port IA_AD
IB_AD: U27.21(A10/C10/GPIO230) ; port IB_AD
IC_AD: U27.8(A11/C0) ; port IC_AD
LED1C_C2K: D25.2(K) U27.27(GPIO24)
MCU_TCK: C151.1 J11.3 R153.1 U27.28(TCK)
MCU_TMS: C150.1 J11.2 R152.1 U27.30(TMS)
PWMA: R155.2 U27.38(GPIO4) ; port PWMA
PWMB: U27.40(GPIO2) ; port PWMB
PWMC: U27.48(GPIO6) ; port PWMC
RELAY: U27.26(GPIO16) ; port RELAY
RX: R147.2 ; port UART_RX_ISO
SYS_RX: R146.1 U27.2(A16/C16/GPIO28)
SYS_TX: R149.1 U27.1(GPIO29)
TMPA: U27.6(A2/C9/GPIO224) ; port TMPA
TMPB: U27.5(A3/C5/GPIO242) ; port TMPB
TMPC: U27.14(A12/C1) ; port TMPC
TX: R148.2 ; port UART_TX_ISO
V_BUSN_AD: U27.11(A0/C15/CMP1_DACL) ; port V_BUSN_AD
V_BUSP_AD: U27.9(A5/C2) ; port V_BUSP_AD
VA_AD: U27.20(A9/C8/GPIO227) ; port VA_AD
VB_AD: U27.23(A19/C19/GPIO13) ; port VB_AD
VC_AD: U27.24(A20/C20/GPIO12) ; port VC_AD
XRSn: C149.2 R154.2 U27.3(~{XRS})
NetC143_2: C143.2 R144.2 TP22.1
NetC144_2: C144.2 R145.2 TP23.1
NetC146_1: C146.1 C147.2 C148.1 U27.36(VDD) U27.45(VDD)
NetC156_1: C156.1 U27.12(VREFHI)
NetC157_2: C157.2 R158.2 TP27.1
NetD25_1: D25.1(A) R156.2
NetR146_2: R146.2 U26.2(OUTA)
NetR147_1: R147.1 U26.7(INA)
NetR148_1: R148.1 U26.6(OUTB)
NetR149_2: R149.2 U26.3(INB)
NetR151_1: R151.1 U27.39(GPIO3)
NetR157_1: R157.1 TP26.1 U27.32(GPIO32)
NetR158_1: R158.1 U27.25(GPIO33)

Not connected (* = marked no-connect by the designer): U27 4(A6/C6/GPIO226/GPIO228) 7(A14/A15/C4/C7) 10(A1) 16(A8/C11) 29(GPIO37/TDO) 31(GPIO35/TDI) 41(GPIO1) 42(GPIO0) 47(GPIO5)

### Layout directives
net class PGND: 3.3V, 5V_ISO, A3.3V, DAC0, DAC1, GND, GND_ISO, HS_TEMP_AD, LED1C_C2K, MCU_TCK, MCU_TMS, SYS_RX, SYS_TX, XRSn

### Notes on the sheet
- Controller
- Debugging DAC
- (near TP24) GND Connector
- (near R158) DAC
- Profiling GPIO

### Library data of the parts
C141 C142 = CMP-0079720-2: as C78 on sheet InputVoltageSensing
C143-C146 C148 C149 C152 C153 C157 = CMP-0095617-1: as C79 on sheet InputVoltageSensing
C147 C154 C155 = CMP-0007497-5: CAP, CERM, 10 uF, 10 V, +/- 20%, X7R, 0603; Manufacturer: MuRata; TaMin_C: -55°C; Polarized: N; SizeAreaWB_mm2: 4.68; Value1: Unknown; U/M: EA; Value: 10uF; TaMax_C: 125°C; SizeZ_mm: 1; SizeX_mm: 1.6; SizeY_mm: 0.8; SizeArea_mm2: 1.28; AEC Category: Q200
C150 C151 = CMP-0007237-4: as C83 on sheet InputVoltageSensing
C156 = CMP-0084284-1: CAP, CERM, 2.2 µF, 10 V,+/- 10%, X7R, AEC-Q200 Grade 1, 0603; Manufacturer: MuRata; SizeAreaWB_mm2: 4.68; Polarized: N; AEC Qualified: Y; SizeX_mm: 1.6; SizeZ_mm: 1; SizeY_mm: 0.8; U/M: EA; TaMin_C: -55°C; Value: 2.2uF; AEC Category: Q200; TaMax_C: 125°C; SizeArea_mm2: 1.28
D25 = CMP-0079922-3: LED, Red, SMD; Manufacturer: Lite-On; SizeX_mm: 1.6; Value2: 2V; SizeY_mm: 0.8; Green_REACh: Incomplete; SizeAreaWB_mm2: 4.68; Green_Lifecycle: Not Set; Value1: W; Io_A: 5mA; Type: AlInGaP; SizeZ_mm: 0.45; Tjmax_C: 85°C; SizeArea_mm2: 1.28
J11 = CMP-0054798-2: Header, 2.54 mm, 4x1, Gold, TH; Manufacturer: Wurth Elektronik; Pitch_mm: 2.54; Gender: Male; Row_Count: 1; Cert_UL: Y; Shrouded: N
J12 = CMP-0054794-2: Header, 2.54 mm, 2x1, Gold, TH; Manufacturer: Wurth Elektronik; Shrouded: N; Gender: Male; Green_REACh: Passed; Pitch_mm: 2.54; Green_Lifecycle: Active; Row_Count: 1; Cert_UL: Y
L10 = CMP-0003201-2: Ferrite Bead, 1000 ohm @ 100 MHz, 0.6 A, 0603; Manufacturer: Wurth Elektronik; Ztyp@1GHz_Ohm: 185.971; ZTyp@100MHz_Ohm: 1k; SizeAreaWB_mm2: 4.68; DCR_ohm: 0.3; Value1: 0.3 ohm; Imax_A: 600mA; SizeZ_mm: 1; SizeX_mm: 1.6; SizeY_mm: 0.8; Value2: 0.6A; SizeArea_mm2: 1.28
R144 R145 R147 R149 R150 R156-R158 = CMP-0022895-5: RES, 1.00 k, 1%, 0.1 W, 0603; Manufacturer: Yageo; Power_W: 100mW; TempCo: 100 ppm/C; Value_Code: 1k00; Value: 1.00k; EIA_Code: E96; Res_ohm: 1k; SizeX_mm: 1.6; SizeY_mm: 0.8; SizeZ_mm: 1; Value2: 0.1W; SizeArea_mm2: 1.28; AEC Qualified: N; VDC_V: 75V; AEC Category: Q200; SizeAreaWB_mm2: 4.68
R146 R148 = CMP-0022736-4: as R1 on sheet EMCInputFilter
R151 R154 R155 = CMP-0022746-5: as R2 on sheet EMCInputFilter
R152 R153 = CMP-0022991-5: RES, 2.40 k, 1%, 0.1 W, 0603; Manufacturer: Yageo; Power_W: 100mW; TempCo: 100 ppm/C; Value_Code: 2k40; Value: 2.40k; Res_ohm: 2.4k; SizeX_mm: 1.6; SizeY_mm: 0.8; SizeZ_mm: 1; Value2: 0.1W; SizeArea_mm2: 1.28; AEC Qualified: N; VDC_V: 75V; AEC Category: Q200; SizeAreaWB_mm2: 4.68
RT2 = CMP-0084566-1: Thermistor, DEC0002A (X1SON-2); Alternate Manufacturer: Texas Instruments; Alternate PartNumber: TMP6131DECT; CompType: IC; AEC Category: Q200; SizeX_mm: 1; AEC Qualified: N; SizeZ_mm: 0.5; SizeArea_mm2: 0.6; SizeAreaWB_mm2: 3.2
TP22-TP27 = CMP-0055152-2: as TP14-TP16 on sheet InputVoltageSensing
U26 = CMP-0089949-1: Low Speed, General Purpose, Robust EMC, Dual-Channel Digital Isolators; Manufacturer: Texas Instruments; TJmax_C: +150°C; TaMin_C: -40°C; SizeZ_mm: 1.75mm; Min Supply Voltage: 1.71V; Standoff Height: 0.11mm; AEC Qualified: Yes; TaMax_C: +125°C; AEC Grade: Grade 1; Max Supply Voltage: 5.5V; Interface: LVCMOS
U27 = CMP-0096487-1: Real-Time Microcontrollers; Manufacturer: Texas Instruments; Number Of Pwm Channels: 14; Number Of Spi Channels: 1; Memory Type: FLASH; Frequency_Fixed: 120MHz; TaMin_C: -40°C; Number Of I2C Channels: 2; AEC Qualified: No; TaMax_C: +125°C; Number Of Adc Channels: 17; Ram Size: 36KBytes; Min Supply Voltage: 2.8V; Number Of Timers/Counters: 4; Core Architecture: TMS320C28x; Data Bus Width: 32bits; Number Of Uart Channels: 3; SizeZ_mm: 1.6mm; Memory Size: 256KBytes; Standoff Height: 0.5mm; Max Supply Voltage: 3.63V; Number Of I/Os: 25; Interface: I2C,SPI,UART,CAN,SCI,SMBus

## Sheet AuxPower.SchDoc: Auxillary Power Supply
size A4; Date: Not shown in title block; ApprovedBy: Not shown in title block; CheckedBy: Not shown in title block; Author: Not shown in title block; CompanyName: Not shown in title block; DrawnBy: Hely Zhang; Engineer: Not shown in title block; Organization: Not shown in title block; Address1: Not shown in title block; Address2: Not shown in title block; Address3: Not shown in title block; Address4: Not shown in title block; DocumentNumber: 1; Revision: Use project parameter SCH_Rev; SheetNumber: 5; SheetTotal: 11; PageSetup: Record=PageOptions¦CenterHorizontal=True¦CenterVertical=True¦PrintScale=1.00¦XCorrection=1.00¦YCorrection=1.00¦PrintKind=0¦BorderSize=5000000¦LeftOffset=0¦BottomOffset=0¦Orientation=2¦PaperLength=1000¦PaperWidth=1000¦Scale=100¦PaperSource=15¦PrintQuality=600¦MediaType=1¦DitherType=10¦PaperKind=Letter¦PrintScaleMode=1
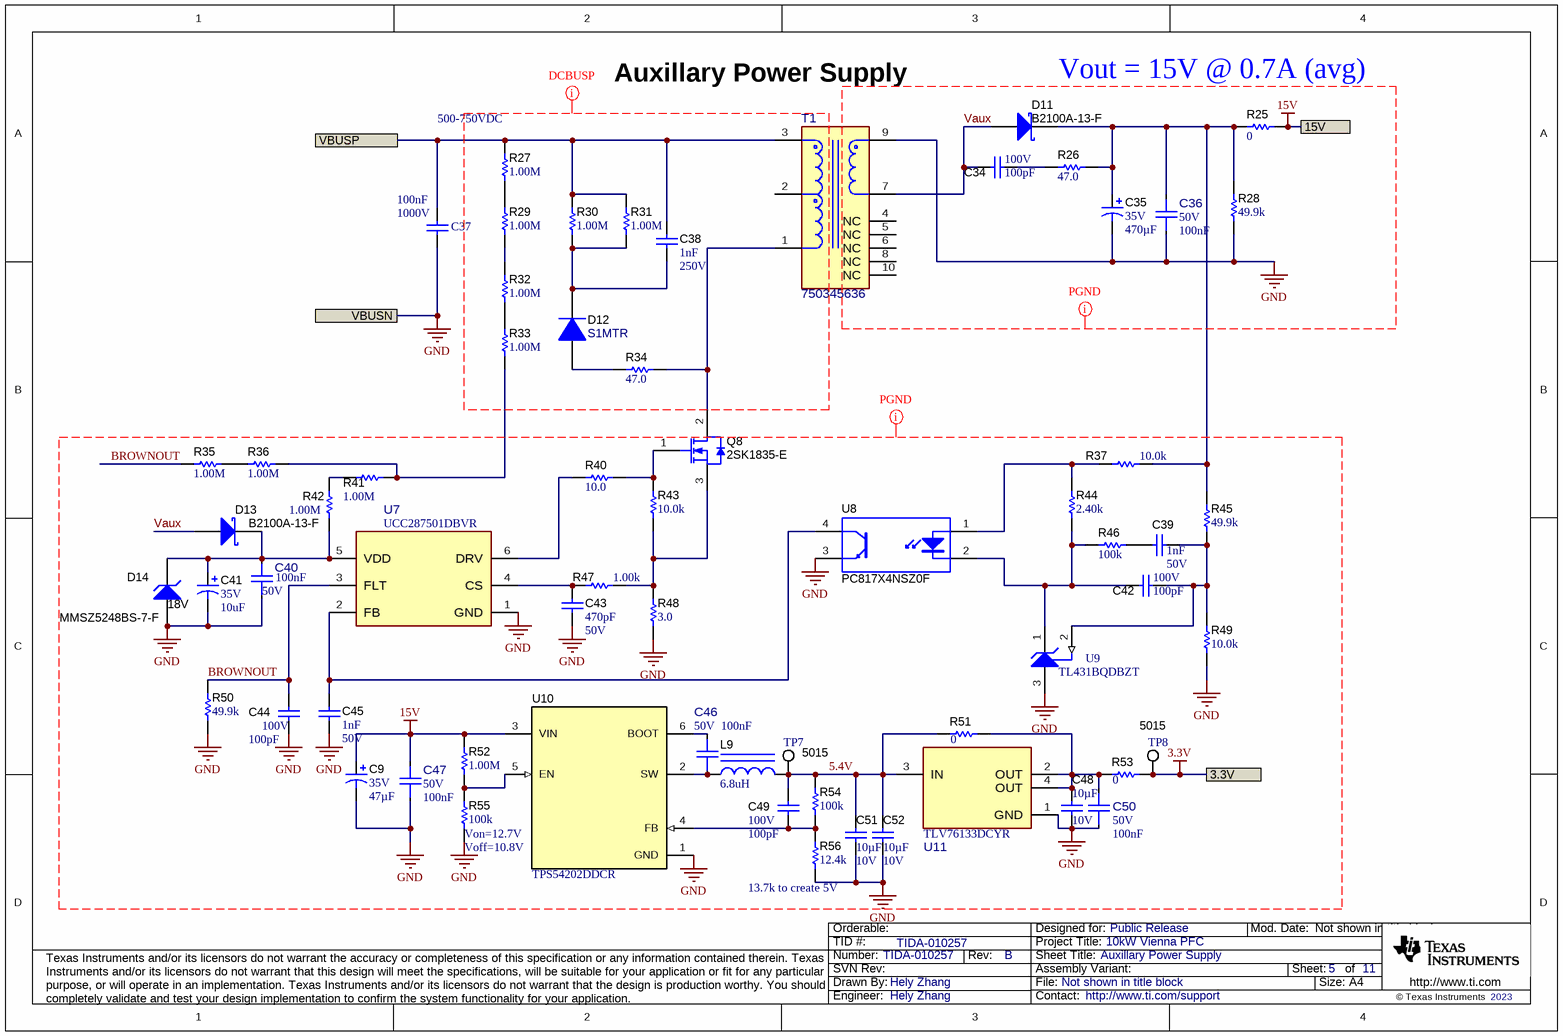
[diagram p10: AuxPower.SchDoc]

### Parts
C9  VDC_V: 35V  ValueDisplayed: 47µF  [Chemi-Con_500x1100]  (hidden comment: EKZN350ELL470ME11D)
C34  VDC_V: 100V  ValueDisplayed: 100pF  [0603]  (hidden comment: GRM1885C2A101JA01D)
C35  VDC_V: 35V  ValueDisplayed: 470µF  [ZLG_1000x2000]  (hidden comment: 35ZLG470MEFC10X20)
C36  VDC_V: 50V  Cap_F: 100nF  [FP-GCM188R71H104KA57J_0603-MFG]  (hidden comment: GCM188R71H104KA57J)
C37  Cap_F: 100nF  Rated Voltage (DC): 1000V  [WCAP-FTBE_L18W8.5H15]  (hidden comment: 890493425009CS)
C38  Cap_F: 1nF  VDC_V: 250V  [0805_HV]  (hidden comment: GRM21AR72E102KW01D)
C39  Cap_F: 1nF  VDC_V: 50V  [0603]  (hidden comment: GRM188R71H102KA01D)
C40  VDC_V: 50V  Cap_F: 100nF  [FP-GCM188R71H104KA57J_0603-MFG]  (hidden comment: GCM188R71H104KA57J)
C41  VDC_V: 35V  ValueDisplayed: 10uF  [PW_500x700]  (hidden comment: UPW1V100MDD6)
C42  VDC_V: 100V  ValueDisplayed: 100pF  [0603]  (hidden comment: GRM1885C2A101JA01D)
C43  Cap_F: 470pF  VDC_V: 50V  [0603]  (hidden comment: 885012206081)
C44  VDC_V: 100V  ValueDisplayed: 100pF  [0603]  (hidden comment: GRM1885C2A101JA01D)
C45  Cap_F: 1nF  VDC_V: 50V  [0603]  (hidden comment: GRM188R71H102KA01D)
C46  VDC_V: 50V  Cap_F: 100nF  [FP-GCM188R71H104KA57J_0603-MFG]  (hidden comment: GCM188R71H104KA57J)
C47  VDC_V: 50V  Cap_F: 100nF  [FP-GCM188R71H104KA57J_0603-MFG]  (hidden comment: GCM188R71H104KA57J)
C48  Cap_F: 10µF  VDC_V: 10V  [0603]  (hidden comment: GRM188Z71A106MA73D)
C49  VDC_V: 100V  ValueDisplayed: 100pF  [0603]  (hidden comment: GRM1885C2A101JA01D)
C50  VDC_V: 50V  Cap_F: 100nF  [FP-GCM188R71H104KA57J_0603-MFG]  (hidden comment: GCM188R71H104KA57J)
C51  Cap_F: 10µF  VDC_V: 10V  [0603]  (hidden comment: GRM188Z71A106MA73D)
C52  Cap_F: 10µF  VDC_V: 10V  [0603]  (hidden comment: GRM188Z71A106MA73D)
D11  B2100A-13-F  [SMA]
D12  S1MTR  [SMA]
D13  B2100A-13-F  [SMA]
D14  MMSZ5248BS-7-F  value 18V  [SOD-323]
L9  ValueDisplayed: 6.8uH  [WE-MAIA_3015]  (hidden comment: 78438335068)
Q8  2SK1835-E  [TO-3P]
R25  ValueDisplayed: 0  [0603]  (hidden comment: RC0603JR-070RL)
R26  ValueDisplayed: 47.0  [1206]  (hidden comment: RC1206FR-0747RL)
R27  ValueDisplayed: 1.00M  [0805_HV]  (hidden comment: ERJ-6ENF1004V)
R28  ValueDisplayed: 49.9k  [0603]  (hidden comment: RC0603FR-0749K9L)
R29  ValueDisplayed: 1.00M  [0805_HV]  (hidden comment: ERJ-6ENF1004V)
R30  ValueDisplayed: 1.00M  [0805_HV]  (hidden comment: ERJ-6ENF1004V)
R31  ValueDisplayed: 1.00M  [0805_HV]  (hidden comment: ERJ-6ENF1004V)
R32  ValueDisplayed: 1.00M  [0805_HV]  (hidden comment: ERJ-6ENF1004V)
R33  ValueDisplayed: 1.00M  [0805_HV]  (hidden comment: ERJ-6ENF1004V)
R34  ValueDisplayed: 47.0  [1206]  (hidden comment: RC1206FR-0747RL)
R35  ValueDisplayed: 1.00M  [0805_HV]  (hidden comment: ERJ-6ENF1004V)
R36  ValueDisplayed: 1.00M  [0805_HV]  (hidden comment: ERJ-6ENF1004V)
R37  ValueDisplayed: 10.0k  [0603]  (hidden comment: RC0603FR-0710KL)
R40  ValueDisplayed: 10.0  [0603]  (hidden comment: RC0603FR-0710RL)
R41  ValueDisplayed: 1.00M  [0805_HV]  (hidden comment: ERJ-6ENF1004V)
R42  ValueDisplayed: 1.00M  [0805_HV]  (hidden comment: ERJ-6ENF1004V)
R43  ValueDisplayed: 10.0k  [0603]  (hidden comment: RC0603FR-0710KL)
R44  ValueDisplayed: 2.40k  [0603]  (hidden comment: RC0603FR-072K4L)
R45  ValueDisplayed: 49.9k  [0603]  (hidden comment: RC0603FR-0749K9L)
R46  ValueDisplayed: 100k  [0603]  (hidden comment: RC0603FR-07100KL)
R47  ValueDisplayed: 1.00k  [0603]  (hidden comment: RC0603FR-071KL)
R48  ValueDisplayed: 3.0  [1206]  (hidden comment: CRCW12063R00JNEA)
R49  ValueDisplayed: 10.0k  [0603]  (hidden comment: RC0603FR-0710KL)
R50  ValueDisplayed: 49.9k  [0603]  (hidden comment: RC0603FR-0749K9L)
R51  ValueDisplayed: 0  [0603]  (hidden comment: RC0603JR-070RL)
R52  ValueDisplayed: 1.00M  [0603]  (hidden comment: RC0603FR-071ML)
R53  ValueDisplayed: 0  [0603]  (hidden comment: RC0603JR-070RL)
R54  ValueDisplayed: 100k  [0603]  (hidden comment: RC0603FR-07100KL)
R55  ValueDisplayed: 100k  [0603]  (hidden comment: RC0603FR-07100KL)
R56  ValueDisplayed: 12.4k  [0603]  (hidden comment: RC0603FR-0712K4L)
T1  750345636  [FP-750345636_PTH10-MFG]
TP7  5015  [Testpoint_Keystone_Miniature]
TP8  5015  [Testpoint_Keystone_Miniature]
U7  UCC287501DBVR  [DBV0006A-MFG]
U8  PC817X4NSZ0F  [DIP762W60P254L460H350Q4B]
U9  TL431BQDBZT  [DBZ0003A_N]
U10  TPS54202DDCR  [DDC0006A_N]
U11  TLV76133DCYR  [DCY0004A-MFG]

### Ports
3.3V, 15V, VBUSN, VBUSP

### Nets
3.3V: R53.1 TP8.1 ; port 3.3V
15V: C9.1(+) C47.2 R25.1 R52.2 U10.3(VIN) ; port 15V
GND: C9.2(-) C35.2(-) C36.1 C37.1 C40.1 C41.2(-) C43.2 C44.2 C45.1 C47.1 C48.2 C50.1 C51.2 C52.2 D14.2(A) R28.1 R48.1 R49.1 R50.1 R55.1 R56.1 T1.9 U7.1(GND) U8.3(E) U9.3(ANODE) U10.1(GND) U11.1(GND) ; port VBUSN  [project net VBUSN]
5.4V: C49.2 C51.1 C52.1 L9.2 R51.2 R54.2 TP7.1 U11.3(IN)
BROWNOUT: C44.1 R35.1 R50.2 U7.3(FLT)
Vaux: C34.2 D11.2(A) D13.2(A) T1.7
VBUSP: C37.2 C38.1 R27.2 R30.2 R31.2 T1.3 ; port VBUSP
NetC34_1: C34.1 R26.1
NetC35_1: C35.1(+) C36.2 D11.1(K) R25.2 R26.2 R28.2 R37.2 R45.2
NetC38_2: C38.2 D12.1(K) R30.1 R31.1
NetC39_1: C39.1 R46.1
NetC39_2: C39.2 C42.1 R45.1 R49.2 U9.2(REF)
NetC40_2: C40.2 C41.1(+) D13.1(K) D14.1(K) R42.2 U7.5(VDD)
NetC42_2: C42.2 R44.1 R46.2 U8.2(K) U9.1(CATHODE)
NetC43_1: C43.1 R47.1 U7.4(CS)
NetC45_2: C45.2 U7.2(FB) U8.4(C)
NetC46_1: C46.1 L9.1 U10.2(SW)
NetC46_2: C46.2 U10.6(BOOT)
NetC48_1: C48.1 C50.2 R51.1 R53.2 U11.2(OUT) U11.4(OUT)
NetC49_1: C49.1 R54.1 R56.2 U10.4(FB)
NetD12_2: D12.2(A) R34.1
NetQ8_1: Q8.1(G) R40.2 R43.2
NetQ8_2: Q8.2(D) R34.2 T1.1
NetQ8_3: Q8.3(S) R43.1 R47.2 R48.2
NetR27_1: R27.1 R29.2
NetR29_1: R29.1 R32.2
NetR32_1: R32.1 R33.2
NetR33_1: R33.1 R36.2 R41.1
NetR35_2: R35.2 R36.1
NetR37_1: R37.1 R44.2 U8.1(A)
NetR40_1: R40.1 U7.6(DRV)
NetR41_2: R41.2 R42.1
NetR52_1: R52.1 R55.2 U10.5(EN)

Not connected (* = marked no-connect by the designer): T1 2 4(NC) 5(NC) 6(NC) 8(NC) 10(NC)

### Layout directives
net class PGND: 3.3V, 5.4V, 15V, BROWNOUT, GND, Vaux
net class DCBUSP: (no net found under the mark)

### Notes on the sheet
- (near T1) Auxillary Power Supply
- Vout = 15V @ 0.7A (avg)
- (near R27) 500-750VDC
- (near R55) Von=12.7V
- Voff=10.8V
- (near R56) 13.7k to create 5V

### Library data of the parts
C9 = CMP-0074695-1: CAP, AL, 47 µF, 35 V, +/- 20%, 0.38 ohm, TH; Manufacturer: Chemi-Con; TaMin_C: -40°C; ESR_ohm: 0.38; Polarized: Y; SizeAreaWB_mm2: 49.0; U/M: EA; Value: 47uF; TaMax_C: 105°C; SizeZ_mm: 12.5; SizeX_mm: 5.0; Cap_Case: 5x11; SizeArea_mm2: 25.0; CompType: Capacitor; AEC Qualified: N; IRMS_A: 450mA; AEC Category: Q200
C34 C42 C44 C49 = CMP-0007237-4: as C83 on sheet InputVoltageSensing
C35 = CMP-0078291-1: CAP, AL, 470 µF, 35 V, +/- 20%, TH; Manufacturer: Rubycon; IRMS_A: 2.18A; SizeAreaWB_mm2: 144; SizeArea_mm2: 100; AEC Qualified: N; AEC Category: Q200; Value: 470uF; TaMax_C: 105°C; SizeZ_mm: 22; Polarized: Y; TaMin_C: -40°C; SizeY_mm: 10; U/M: EA; CompType: Capacitor; Cap_Case: 10x20mm
C36 C40 C46 C47 C50 = CMP-0095617-1: as C79 on sheet InputVoltageSensing
C37 = CMP-0116358-1: WCAP-FTBE Film Capacitor, THT, L18 x W8.5 x H15mm, 100nF, 1000V; Manufacturer: Wurth Elektronik; Capacitance Tolerance: +/-10%; Dissipation Factor @100kHz: 2.5%; Dissipation Factor @10kHz: 1.4%; Dissipation Factor @1kHz: 1%; Insulation Resistance: 9000MOhm; Pitch: 15mm; Rate of Voltage Rise: 44V/us; Technical Reference: MPSP015104KA00DCPP45004
C38 = CMP-0008251-1: CAP, CERM, 1000 pF, 250 V, +/- 10%, X7R, 0805; Manufacturer: MuRata; TaMin_C: -55°C; Polarized: N; SizeAreaWB_mm2: 6.75; Value1: Unknown; U/M: EA; Value: 1000pF; TaMax_C: 125°C; SizeZ_mm: 1.45; SizeX_mm: 2; SizeY_mm: 1.25; Cap_Case: 0805; SizeArea_mm2: 2.5; AEC Category: Q200
C39 C45 = CMP-0007432-5: as C80 on sheet InputVoltageSensing
C41 = CMP-0010551-1: CAP, AL, 10 uF, 35 V, +/- 20%, 0.95 ohm, TH; Manufacturer: Nichicon; TaMin_C: -55°C; ESR_ohm: 0.95; Polarized: Y; SizeAreaWB_mm2: 49; U/M: EA; Value: 10uF; TaMax_C: 105°C; SizeZ_mm: 8; SizeX_mm: 5; Cap_Case: 5x7; SizeArea_mm2: 25; CompType: Capacitor; Cap_F: 10µF; IRMS_A: 120mA; AEC Category: Q200
C43 = CMP-0006834-5: CAP, CERM, 470 pF, 50 V, +/- 10%, X7R, 0603; Manufacturer: Wurth Elektronik; TaMin_C: -55°C; Polarized: N; SizeAreaWB_mm2: 4.68; Value1: Unknown; U/M: EA; Value: 470pF; TaMax_C: 125°C; SizeZ_mm: 1; SizeX_mm: 1.6; SizeY_mm: 0.8; SizeArea_mm2: 1.28; AEC Category: Q200
C48 C51 C52 = CMP-0007497-5: as C147 on sheet Controller
D11 D13 = CMP-0081099-1: Diode, Schottky, 100 V, 2 A, SMA; Manufacturer: Diodes Inc.; SizeAreaWB_mm2: 37.3428; Vr_V: 100V; SizeArea_mm2: 16.3228; AEC Qualified: N; TJmax_C: 125°C; AEC Category: Q101; Value: 100V; SizeZ_mm: 2.87; Io_A: 2A; Vf_V: 7.9dV; SizeY_mm: 2.92; Value2: 0.79V; SizeX_mm: 5.59
D12 = CMP-0078438-1: Diode, Standard Recovery Rectifier, 1000 V, 1 A, SMA; Manufacturer: SMC Diode Solutions; SizeAreaWB_mm2: 37.3428; Vr_V: 1kV; SizeArea_mm2: 16.3228; AEC Qualified: N; TJmax_C: 175°C; AEC Category: Q101; Value: 1000V; SizeZ_mm: 2.87; Io_A: 1A; Vf_V: 1.1V; SizeY_mm: 2.92; SizeX_mm: 5.59
D14 = CMP-0005835-4: Diode, Zener, 18 V, 200 mW, SOD-323; Manufacturer: Diodes Inc.; Value1: 0.2W; SizeArea_mm2: 3.645; AEC Category: Q101; Power_W: 200mW; SizeAreaWB_mm2: 8.695; SizeY_mm: 1.35; RJA_CperW: 350; SizeZ_mm: 1; SizeX_mm: 2.7
L9 = CMP-0064362-1: Inductor, Shielded, Powdered Iron, 6.8 uH, 1.1 A, 0.287 ohm, AEC-Q200 Grade 1, SMD; Manufacturer: Wurth Elektronik; Isat: 2.4A @ 20% inductance drop; Irms: 1.1A @ 40C rise; SizeAreaWB_mm2: 16; DCR_ohm: 0.287; Value: 6.8uH; Imax_A: 1.1A; SizeZ_mm: 1.5; SizeX_mm: 3; SizeArea_mm2: 9; Ind_H: 6.8µH; AEC Qualified: Y; AEC Grade: 1; AEC Category: Q200
Q8 = CMP-0082176-2: MOSFET, N-CH, 1500 V, 4 A, TO-3P; Alternate Manufacturer: None; Manufacturer: Renesas; IdsMax_A: 4A; Vgs_V: 20V; Value: 1500V; SizeX_mm: 15.65; SizeY_mm: 4.8; ChType: N; SizeAreaWB_mm2: 120.02; Value1: ? ohm; SizeZ_mm: 23.9; VdsMax_V: 1.5kV; SizeArea_mm2: 75.12; AEC Category: Q101; Value2: ? nC; ChMode: Enhancement
R25 R51 R53 = CMP-0025885-5: as R12 on sheet EMCInputFilter
R26 R34 = CMP-0018320-2: RES, 47.0, 1%, 0.25 W, 1206; Manufacturer: Yageo America; Power_W: 250mW; TempCo: 100 ppm/C; Value_Code: 47R0; U/M: EA; Value: 47.0; Res_ohm: 47; SizeX_mm: 3.2; SizeY_mm: 1.6; SizeZ_mm: 1.35; Value2: 0.25W; SizeArea_mm2: 5.12; VDC_V: 200V; AEC Category: Q200
R27 R29-R33 R35 R36 R41 R42 = CMP-0021522-3: as R3-R11 on sheet EMCInputFilter
R28 R45 R50 = CMP-0023142-5: RES, 49.9 k, 1%, 0.1 W, 0603; Manufacturer: Yageo; Power_W: 100mW; TempCo: 100 ppm/C; Value_Code: 49k9; Value: 49.9k; EIA_Code: E96; SizeX_mm: 1.6; SizeY_mm: 0.8; SizeZ_mm: 1; Value2: 0.1W; SizeArea_mm2: 1.28; AEC Qualified: N; VDC_V: 75V; AEC Category: Q200; SizeAreaWB_mm2: 4.68
R37 R43 R49 = CMP-0022746-5: as R2 on sheet EMCInputFilter
R40 = CMP-0022751-4: as R95 on sheet InputVoltageSensing
R44 = CMP-0022991-5: as R152 on sheet Controller
R46 R54 R55 = CMP-0022735-5: as R122 on sheet OutputVoltageSensing
R47 = CMP-0022895-5: as R144 on sheet Controller
R48 = CMP-0018676-1: RES, 3.0, 5%, 0.25 W, 1206; Manufacturer: Vishay-Dale; Power_W: 250mW; TempCo: 200 ppm/C; Value_Code: 3R00; U/M: EA; Value: 3.0; EIA_Code: E24; Res_ohm: 3; SizeX_mm: 3.2; SizeY_mm: 1.6; SizeZ_mm: 1.35; Value2: 0.25W; SizeArea_mm2: 5.12; VDC_V: 200V; AEC Category: Q200
R52 = CMP-0022899-4: RES, 1.00 M, 1%, 0.1 W, 0603; Manufacturer: Yageo; Power_W: 100mW; TempCo: 100 ppm/C; Value_Code: 1M00; Value: 1.00Meg; EIA_Code: E96; Res_ohm: 1M; SizeX_mm: 1.6; SizeY_mm: 0.8; SizeZ_mm: 1; Value2: 0.1W; SizeArea_mm2: 1.28; AEC Qualified: N; VDC_V: 75V; AEC Category: Q200; SizeAreaWB_mm2: 4.68
R56 = CMP-0022777-5: as R79 on sheet InputVoltageSensing
T1 = CMP-0122470-1: TRANSFORMER; Manufacturer: Wurth Electornics; Ind_H: 12mH; Ns1toNp: 18.89:1; SizeZ_mm: 21mm; AEC Qualified: No; Frequency_Fixed: 100kHz; Voltage_Isolation_Vrms: 3.2kV
TP7 TP8 = CMP-0055152-2: as TP14-TP16 on sheet InputVoltageSensing
U7 = CMP-0121336-1: Current-Mode Flyback Controller with Secondary-Side Regulation (SSR) for Off-Line Applications; Manufacturer: Texas Instruments; SizeZ_mm: 1.45mm; AEC Qualified: No; Max Duty Cycle: 80%; Max Supply Voltage: 26V; Min Supply Voltage: 10V; Nominal Supply Current: 1.8mA; Number Of Outputs: 1; Standoff Height: 0mm; Switching Frequency: 65kHz; TJmax_C: +125°C
U8 = CMP-0006159-2: Optocoupler, 5 kV, 50% min CTR, TH; Manufacturer: Sharp Microelectronics; SizeAreaWB_mm2: 63.2996; SizeZ_mm: 7.5; SizeX_mm: 7.62; SizeY_mm: 4.58; SizeArea_mm2: 34.8996; Voltage_Isolation_Vrms: 5kV
U9 = CMP-0032994-1: Adjustable Precision Shunt Regulator, 34 ppm / degC, 100 mA, -40 to 125 degC, 3-pin SOT-23 (DBZ), Green (RoHS & no Sb/Br); Manufacturer: Texas Instruments; VO Adj(Max)(V): 36; Iout/Iz(Max)(mA): 100; SubFamily: Shunt Voltage Reference; Temp Coeff(Max)(ppm/ degree C): 92; Initial Accuracy @ 25/deg C(%): 0.5; Rating: Catalog; Temp Coeff(Typ)(ppm/ degree C): 34; Min Iz for Regulation(uA): 600; VO Adj(Min)(V): 2.495
U10 = CMP-0073969-3: 4.5V to 28V Input, 2A Output, EMI Friendly Synchronous Step-Down Converter, DDC0006A (SOT-23-THIN-6); Alternate PartNumber: TPS54202DDCT; Manufacturer: Texas Instruments; SizeZ_mm: 0.87; SizeX_mm: 1.65; SizeY_mm: 2.95; SizeArea_mm2: 4.8675; CompType: IC; SizeAreaWB_mm2: 10.4675; AEC Category: Q200; AEC Qualified: N; Rating: Catalog
U11 = CMP-0122558-1: 1-A 16-V high-PSRR linear voltage regulator 4-SOT-223 -40 to 125; Manufacturer: Texas Instruments; SizeZ_mm: 1.8mm; AEC Qualified: No; Accuracy Percentage: 1%; Dropout Voltage: 0.9V; Max Supply Voltage: 16V; Min Supply Voltage: 4.8V; Nominal Supply Current: 65uA; Number Of Outputs: 1; Output Type: Fixed; Output Voltage: 3.3V; Standoff Height: 0.02mm; TJmax_C: +125°C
